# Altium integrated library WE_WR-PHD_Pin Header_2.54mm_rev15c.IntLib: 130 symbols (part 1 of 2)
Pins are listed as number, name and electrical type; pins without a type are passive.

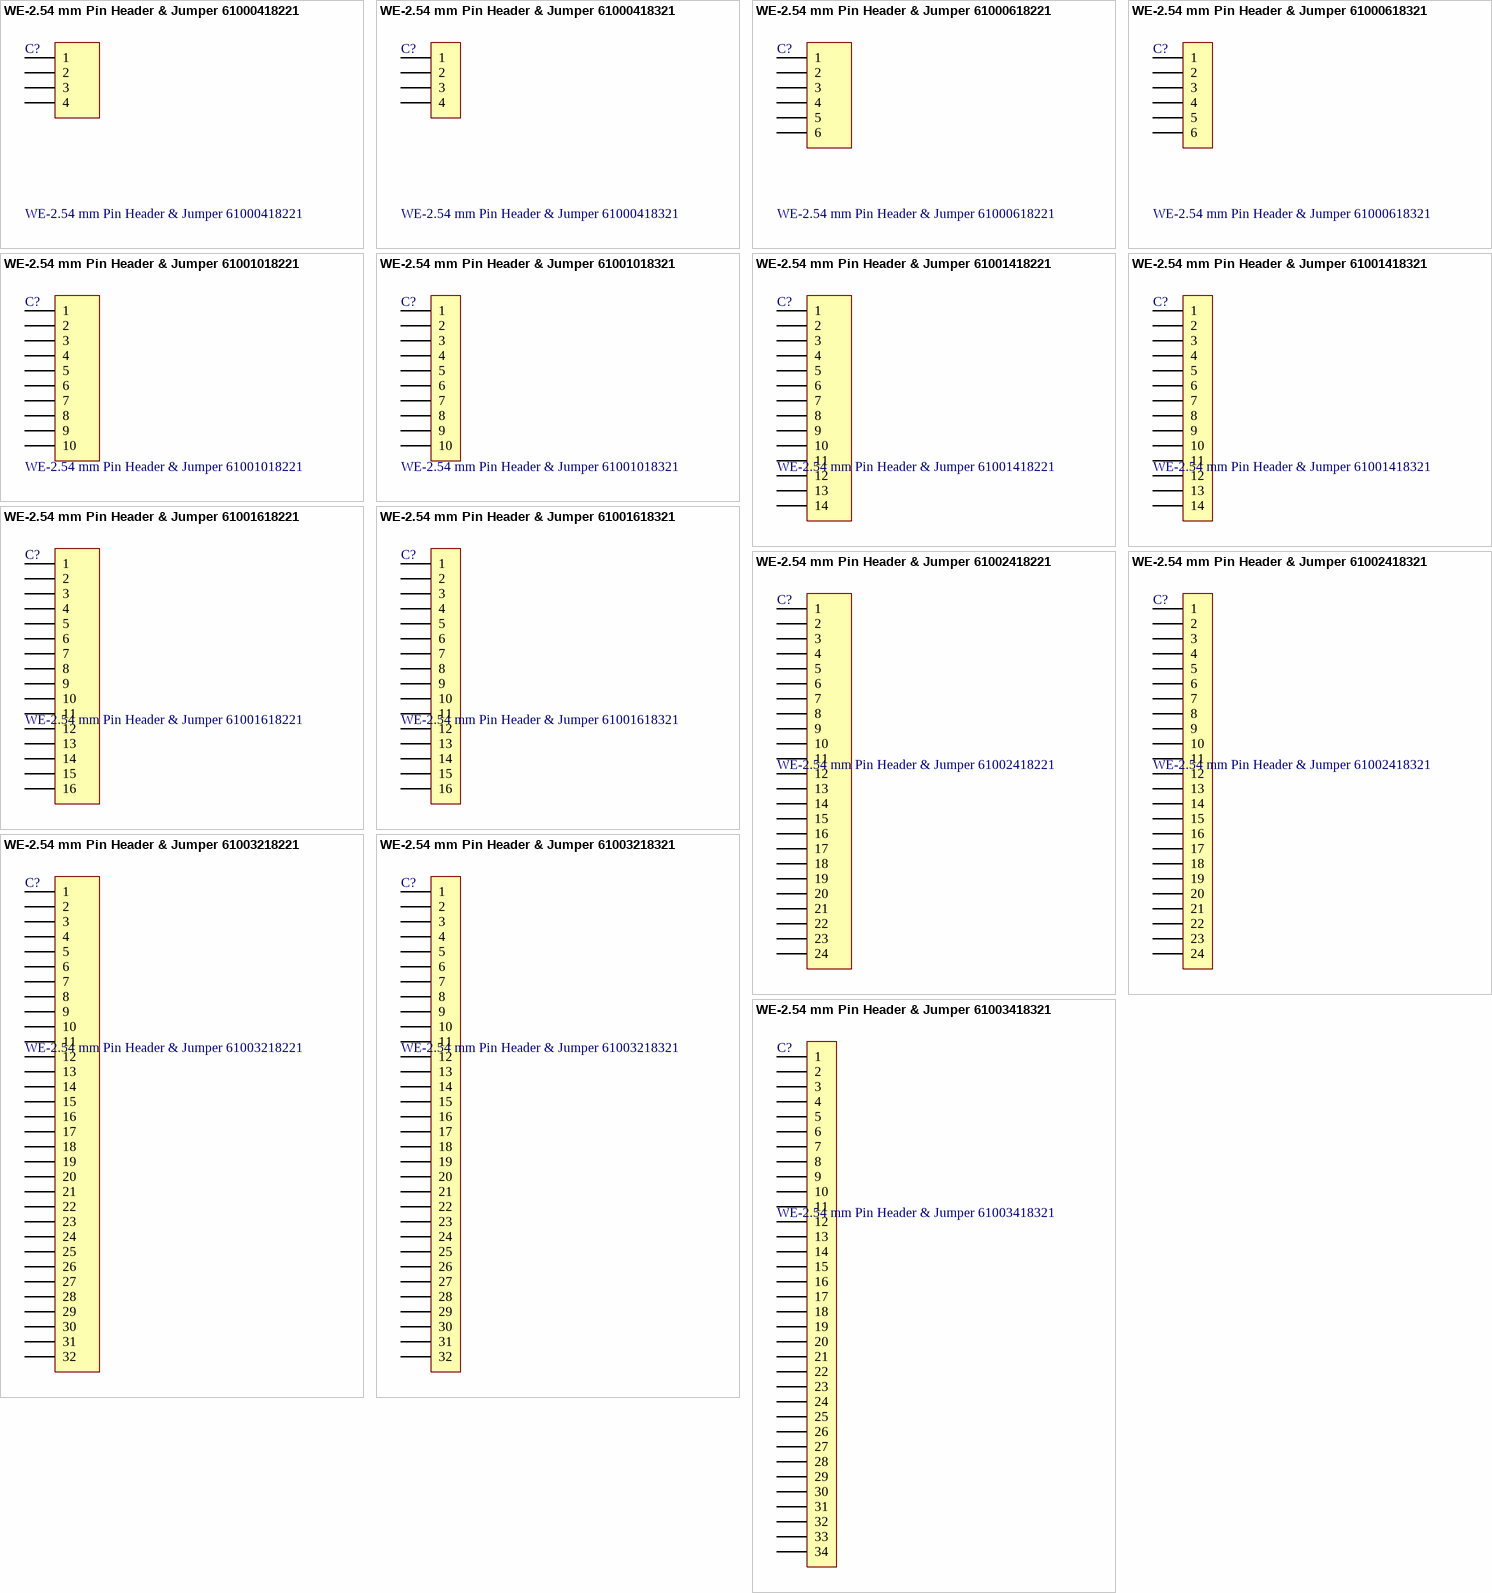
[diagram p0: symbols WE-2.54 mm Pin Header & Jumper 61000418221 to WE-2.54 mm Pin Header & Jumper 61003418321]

## WE-2.54 mm Pin Header & Jumper 61000418221
designator C?
WR-PHD 2.54 mm SMT Pin Header; Manufacturer: Würth Elektronik eiSos GmbH; ComponentLink1 Description: Manufacturer; ComponentLink2 Description: Datasheet; NoPins: 04
footprint 61000418221 (SMT, 4 pins, 1 row, straight, Type 1, gold plating)
pins: 1, 2, 3, 4

## WE-2.54 mm Pin Header & Jumper 61000418321
designator C?
WR-PHD 2.54 mm SMT Pin Header; Manufacturer: Würth Elektronik eiSos GmbH; ComponentLink1 Description: Manufacturer; ComponentLink2 Description: Datasheet; NoPins: 04
footprint 61000418321 (SMT, 4 pins, 1 row, straight, Type 2, gold plating)
pins: 1, 2, 3, 4

## WE-2.54 mm Pin Header & Jumper 61000618221
designator C?
WR-PHD 2.54 mm SMT Pin Header; Manufacturer: Würth Elektronik eiSos GmbH; ComponentLink1 Description: Manufacturer; ComponentLink2 Description: Datasheet; NoPins: 06
footprint 61000618221 (SMT, 6 pins, 1 row, straight, Type 1, gold plating)
pins: 1, 2, 3, 4, 5, 6

## WE-2.54 mm Pin Header & Jumper 61000618321
designator C?
WR-PHD 2.54 mm SMT Pin Header; Manufacturer: Würth Elektronik eiSos GmbH; ComponentLink1 Description: Manufacturer; ComponentLink2 Description: Datasheet; NoPins: 06
footprint 61000618321 (SMT, 6 pins, 1 row, straight, Type 2, gold plating)
pins: 1, 2, 3, 4, 5, 6

## WE-2.54 mm Pin Header & Jumper 61001018221
designator C?
WR-PHD 2.54 mm SMT Pin Header; Manufacturer: Würth Elektronik eiSos GmbH; ComponentLink1 Description: Manufacturer; ComponentLink2 Description: Datasheet; NoPins: 10
footprint 61001018221 (SMT, 10 pins, 1 row, straight, Type 1, gold plating)
pins: 1, 2, 3, 4, 5, 6, 7, 8, 9, 10

## WE-2.54 mm Pin Header & Jumper 61001018321
designator C?
WR-PHD 2.54 mm SMT Pin Header; Manufacturer: Würth Elektronik eiSos GmbH; ComponentLink1 Description: Manufacturer; ComponentLink2 Description: Datasheet; NoPins: 10
footprint 61001018321 (SMT, 10 pins, 1 row, straight, Type 2, gold plating)
pins: 1, 2, 3, 4, 5, 6, 7, 8, 9, 10

## WE-2.54 mm Pin Header & Jumper 61001418221
designator C?
WR-PHD 2.54 mm SMT Pin Header; Manufacturer: Würth Elektronik eiSos GmbH; ComponentLink1 Description: Manufacturer; ComponentLink2 Description: Datasheet; NoPins: 14
footprint 61001418221 (SMT, 14 pins, 1 row, straight, Type 1, gold plating)
pins: 1, 2, 3, 4, 5, 6, 7, 8, 9, 10, 11, 12, 13, 14

## WE-2.54 mm Pin Header & Jumper 61001418321
designator C?
WR-PHD 2.54 mm SMT Pin Header; Manufacturer: Würth Elektronik eiSos GmbH; ComponentLink1 Description: Manufacturer; ComponentLink2 Description: Datasheet; NoPins: 14
footprint 61001418321 (SMT, 14 pins, 1 row, straight, Type 2, gold plating)
pins: 1, 2, 3, 4, 5, 6, 7, 8, 9, 10, 11, 12, 13, 14

## WE-2.54 mm Pin Header & Jumper 61001618221
designator C?
WR-PHD 2.54 mm SMT Pin Header; Manufacturer: Würth Elektronik eiSos GmbH; ComponentLink1 Description: Manufacturer; ComponentLink2 Description: Datasheet; NoPins: 16
footprint 61001618221 (SMT, 16 pins, 1 row, straight, Type 1, gold plating)
pins: 1, 2, 3, 4, 5, 6, 7, 8, 9, 10, 11, 12, 13, 14, 15, 16

## WE-2.54 mm Pin Header & Jumper 61001618321
designator C?
WR-PHD 2.54 mm SMT Pin Header; Manufacturer: Würth Elektronik eiSos GmbH; ComponentLink1 Description: Manufacturer; ComponentLink2 Description: Datasheet; NoPins: 16
footprint 61001618321 (SMT, 16 pins, 1 row, straight, Type 2, gold plating)
pins: 1, 2, 3, 4, 5, 6, 7, 8, 9, 10, 11, 12, 13, 14, 15, 16

## WE-2.54 mm Pin Header & Jumper 61002418221
designator C?
WR-PHD 2.54 mm SMT Pin Header; Manufacturer: Würth Elektronik eiSos GmbH; ComponentLink1 Description: Manufacturer; ComponentLink2 Description: Datasheet; NoPins: 24
footprint 61002418221 (SMT, 24 pins, 1 row, straight, Type 1, gold plating)
pins: 1, 2, 3, 4, 5, 6, 7, 8, 9, 10, 11, 12, 13, 14, 15, 16, 17, 18, 19, 20, 21, 22, 23, 24

## WE-2.54 mm Pin Header & Jumper 61002418321
designator C?
WR-PHD 2.54 mm SMT Pin Header; Manufacturer: Würth Elektronik eiSos GmbH; ComponentLink1 Description: Manufacturer; ComponentLink2 Description: Datasheet; NoPins: 24
footprint 61002418321 (SMT, 24 pins, 1 row, straight, Type 2, gold plating)
pins: 1, 2, 3, 4, 5, 6, 7, 8, 9, 10, 11, 12, 13, 14, 15, 16, 17, 18, 19, 20, 21, 22, 23, 24

## WE-2.54 mm Pin Header & Jumper 61003218221
designator C?
WR-PHD 2.54 mm SMT Pin Header; Manufacturer: Würth Elektronik eiSos GmbH; ComponentLink1 Description: Manufacturer; ComponentLink2 Description: Datasheet; NoPins: 32
footprint 61003218221 (SMT, 32 pins, 1 row, straight, Type 1, gold plating)
pins: 1, 2, 3, 4, 5, 6, 7, 8, 9, 10, 11, 12, 13, 14, 15, 16, 17, 18, 19, 20, 21, 22, 23, 24, 25, 26, 27, 28, 29, 30, 31, 32

## WE-2.54 mm Pin Header & Jumper 61003218321
designator C?
WR-PHD 2.54 mm SMT Pin Header; Manufacturer: Würth Elektronik eiSos GmbH; ComponentLink1 Description: Manufacturer; ComponentLink2 Description: Datasheet; NoPins: 32
footprint 61003218321 (SMT, 32 pins, 1 row, straight, Type 2, gold plating)
pins: 1, 2, 3, 4, 5, 6, 7, 8, 9, 10, 11, 12, 13, 14, 15, 16, 17, 18, 19, 20, 21, 22, 23, 24, 25, 26, 27, 28, 29, 30, 31, 32

## WE-2.54 mm Pin Header & Jumper 61003418321
designator C?
WR-PHD 2.54 mm SMT Pin Header; Manufacturer: Würth Elektronik eiSos GmbH; ComponentLink1 Description: Manufacturer; ComponentLink2 Description: Datasheet; NoPins: 34
footprint 61003418321 (SMT, 34 pins, 1 row, straight, Type 2, gold plating)
pins: 1, 2, 3, 4, 5, 6, 7, 8, 9, 10, 11, 12, 13, 14, 15, 16, 17, 18, 19, 20, 21, 22, 23, 24, 25, 26, 27, 28, 29, 30, 31, 32, 33, 34

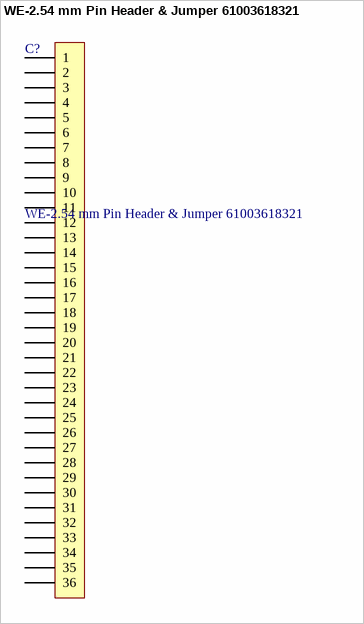
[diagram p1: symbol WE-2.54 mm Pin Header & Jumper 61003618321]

## WE-2.54 mm Pin Header & Jumper 61003618321
designator C?
WR-PHD 2.54 mm SMT Pin Header; Manufacturer: Würth Elektronik eiSos GmbH; ComponentLink1 Description: Manufacturer; ComponentLink2 Description: Datasheet; NoPins: 36
footprint 61003618321 (SMT, 36 pins, 1 row, straight, Type 2, gold plating)
pins: 1, 2, 3, 4, 5, 6, 7, 8, 9, 10, 11, 12, 13, 14, 15, 16, 17, 18, 19, 20, 21, 22, 23, 24, 25, 26, 27, 28, 29, 30, 31, 32, 33, 34, 35, 36


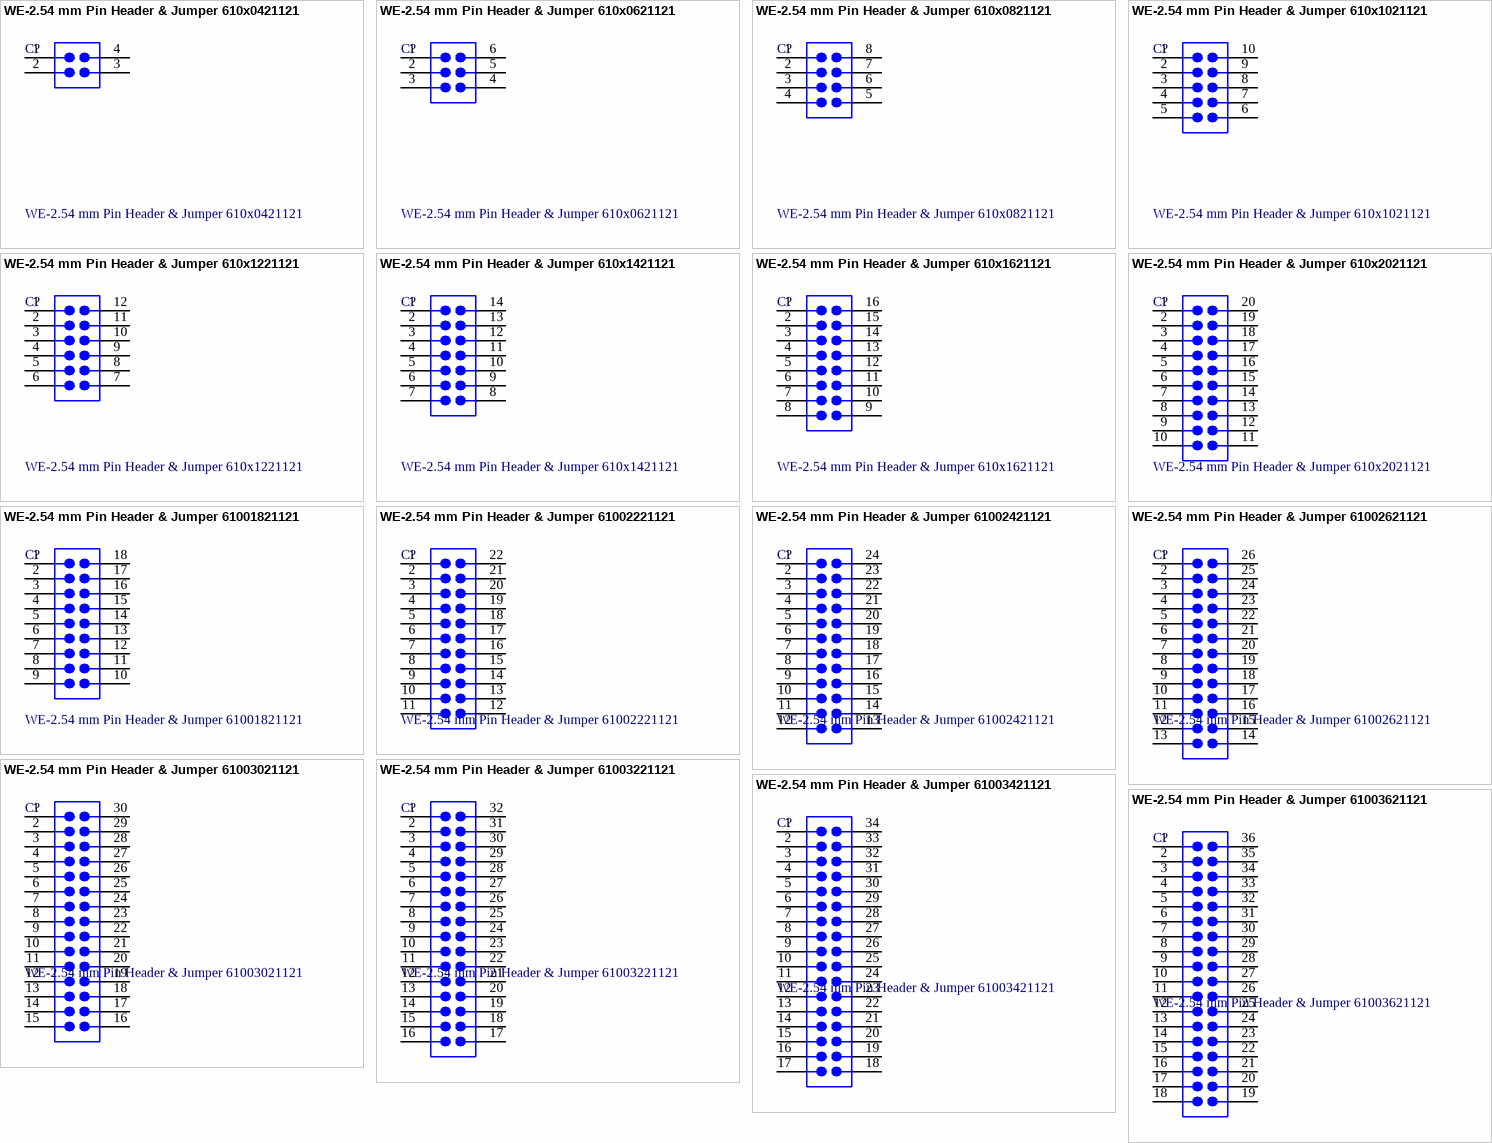
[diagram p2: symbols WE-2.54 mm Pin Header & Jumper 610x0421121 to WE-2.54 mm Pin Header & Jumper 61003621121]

## WE-2.54 mm Pin Header & Jumper 610x0421121
designator C?
WR-PHD 2.54 mm Dual SMT Pin Header; Manufacturer: Würth Elektronik eiSos GmbH; ComponentLink1 Description: Manufacturer; ComponentLink2 Description: Datasheet; NoPins: 04
footprint 610x0421121 (SMT, 4 pins, dual row, straight, gold plating)
pins: 1, 2, 3, 4

## WE-2.54 mm Pin Header & Jumper 610x0621121
designator C?
WR-PHD 2.54 mm Dual SMT Pin Header; Manufacturer: Würth Elektronik eiSos GmbH; ComponentLink1 Description: Manufacturer; ComponentLink2 Description: Datasheet; NoPins: 06
footprint 610x0621121 (SMT, 6 pins, dual row, straight, gold plating)
pins: 1, 2, 3, 4, 5, 6

## WE-2.54 mm Pin Header & Jumper 610x0821121
designator C?
WR-PHD 2.54 mm Dual SMT Pin Header; Manufacturer: Würth Elektronik eiSos GmbH; ComponentLink1 Description: Manufacturer; ComponentLink2 Description: Datasheet; NoPins: 08
footprint 610x0821121 (SMT, 8 pins, dual row, straight, gold plating)
pins: 1, 2, 3, 4, 5, 6, 7, 8

## WE-2.54 mm Pin Header & Jumper 610x1021121
designator C?
WR-PHD 2.54 mm Dual SMT Pin Header; Manufacturer: Würth Elektronik eiSos GmbH; ComponentLink1 Description: Manufacturer; ComponentLink2 Description: Datasheet; NoPins: 10
footprint 610x1021121 (SMT, 10 pins, dual row, straight, gold plating)
pins: 1, 2, 3, 4, 5, 6, 7, 8, 9, 10

## WE-2.54 mm Pin Header & Jumper 610x1221121
designator C?
WR-PHD 2.54 mm Dual SMT Pin Header; Manufacturer: Würth Elektronik eiSos GmbH; ComponentLink1 Description: Manufacturer; ComponentLink2 Description: Datasheet; NoPins: 12
footprint 610x1221121 (SMT, 12  pins, dual row, straight, gold plating)
pins: 1, 2, 3, 4, 5, 6, 7, 8, 9, 10, 11, 12

## WE-2.54 mm Pin Header & Jumper 610x1421121
designator C?
WR-PHD 2.54 mm Dual SMT Pin Header; Manufacturer: Würth Elektronik eiSos GmbH; ComponentLink1 Description: Manufacturer; ComponentLink2 Description: Datasheet; NoPins: 14
footprint 610x1421121 (SMT, 14 pins, dual row, straight, gold plating)
pins: 1, 2, 3, 4, 5, 6, 7, 8, 9, 10, 11, 12, 13, 14

## WE-2.54 mm Pin Header & Jumper 610x1621121
designator C?
WR-PHD 2.54 mm Dual SMT Pin Header; Manufacturer: Würth Elektronik eiSos GmbH; ComponentLink1 Description: Manufacturer; ComponentLink2 Description: Datasheet; NoPins: 16
footprint 610x1621121 (SMT, 16 pins, dual row, straight, gold plating)
pins: 1, 2, 3, 4, 5, 6, 7, 8, 9, 10, 11, 12, 13, 14, 15, 16

## WE-2.54 mm Pin Header & Jumper 610x2021121
designator C?
WR-PHD 2.54 mm Dual SMT Pin Header; Manufacturer: Würth Elektronik eiSos GmbH; ComponentLink1 Description: Manufacturer; ComponentLink2 Description: Datasheet; NoPins: 20
footprint 610x2021121 (SMT, 20 pins, dual row, straight, gold plating)
pins: 1, 2, 3, 4, 5, 6, 7, 8, 9, 10, 11, 12, 13, 14, 15, 16, 17, 18, 19, 20

## WE-2.54 mm Pin Header & Jumper 61001821121
designator C?
WR-PHD 2.54 mm Dual SMT Pin Header; Manufacturer: Würth Elektronik eiSos GmbH; ComponentLink1 Description: Manufacturer; ComponentLink2 Description: Datasheet; NoPins: 18
footprint 61001821121 (SMT, 18 pins, dual row, straight, gold plating)
pins: 1, 2, 3, 4, 5, 6, 7, 8, 9, 10, 11, 12, 13, 14, 15, 16, 17, 18

## WE-2.54 mm Pin Header & Jumper 61002221121
designator C?
WR-PHD 2.54 mm Dual SMT Pin Header; Manufacturer: Würth Elektronik eiSos GmbH; ComponentLink1 Description: Manufacturer; ComponentLink2 Description: Datasheet; NoPins: 22
footprint 61002221121 (SMT, 22 pins, dual row, straight, gold plating)
pins: 1, 2, 3, 4, 5, 6, 7, 8, 9, 10, 11, 12, 13, 14, 15, 16, 17, 18, 19, 20, 21, 22

## WE-2.54 mm Pin Header & Jumper 61002421121
designator C?
WR-PHD 2.54 mm Dual SMT Pin Header; Manufacturer: Würth Elektronik eiSos GmbH; ComponentLink1 Description: Manufacturer; ComponentLink2 Description: Datasheet; NoPins: 24
footprint 61002421121 (SMT, 24 pins, dual row, straight, gold plating)
pins: 1, 2, 3, 4, 5, 6, 7, 8, 9, 10, 11, 12, 13, 14, 15, 16, 17, 18, 19, 20, 21, 22, 23, 24

## WE-2.54 mm Pin Header & Jumper 61002621121
designator C?
WR-PHD 2.54 mm Dual SMT Pin Header; Manufacturer: Würth Elektronik eiSos GmbH; ComponentLink1 Description: Manufacturer; ComponentLink2 Description: Datasheet; NoPins: 26
footprint 61002621121 (SMT, 26 pins, dual row, straight, gold plating)
pins: 1, 2, 3, 4, 5, 6, 7, 8, 9, 10, 11, 12, 13, 14, 15, 16, 17, 18, 19, 20, 21, 22, 23, 24, 25, 26

## WE-2.54 mm Pin Header & Jumper 61003021121
designator C?
WR-PHD 2.54 mm Dual SMT Pin Header; Manufacturer: Würth Elektronik eiSos GmbH; ComponentLink1 Description: Manufacturer; ComponentLink2 Description: Datasheet; NoPins: 30
footprint 61003021121 (SMT, 30 pins, dual row, straight, gold plating)
pins: 1, 2, 3, 4, 5, 6, 7, 8, 9, 10, 11, 12, 13, 14, 15, 16, 17, 18, 19, 20, 21, 22, 23, 24, 25, 26, 27, 28, 29, 30

## WE-2.54 mm Pin Header & Jumper 61003221121
designator C?
WR-PHD 2.54 mm Dual SMT Pin Header; Manufacturer: Würth Elektronik eiSos GmbH; ComponentLink1 Description: Manufacturer; ComponentLink2 Description: Datasheet; NoPins: 32
footprint 61003221121 (SMT, 32 pins, dual row, straight, gold plating)
pins: 1, 2, 3, 4, 5, 6, 7, 8, 9, 10, 11, 12, 13, 14, 15, 16, 17, 18, 19, 20, 21, 22, 23, 24, 25, 26, 27, 28, 29, 30, 31, 32

## WE-2.54 mm Pin Header & Jumper 61003421121
designator C?
WR-PHD 2.54 mm Dual SMT Pin Header; Manufacturer: Würth Elektronik eiSos GmbH; ComponentLink1 Description: Manufacturer; ComponentLink2 Description: Datasheet; NoPins: 34
footprint 61003421121 (SMT, 34 pins, dual row, straight, gold plating)
pins: 1, 2, 3, 4, 5, 6, 7, 8, 9, 10, 11, 12, 13, 14, 15, 16, 17, 18, 19, 20, 21, 22, 23, 24, 25, 26, 27, 28, 29, 30, 31, 32, 33, 34

## WE-2.54 mm Pin Header & Jumper 61003621121
designator C?
WR-PHD 2.54 mm Dual SMT Pin Header; Manufacturer: Würth Elektronik eiSos GmbH; ComponentLink1 Description: Manufacturer; ComponentLink2 Description: Datasheet; NoPins: 36
footprint 61003621121 (SMT, 36 pins, dual row, straight, gold plating)
pins: 1, 2, 3, 4, 5, 6, 7, 8, 9, 10, 11, 12, 13, 14, 15, 16, 17, 18, 19, 20, 21, 22, 23, 24, 25, 26, 27, 28, 29, 30, 31, 32, 33, 34, 35, 36


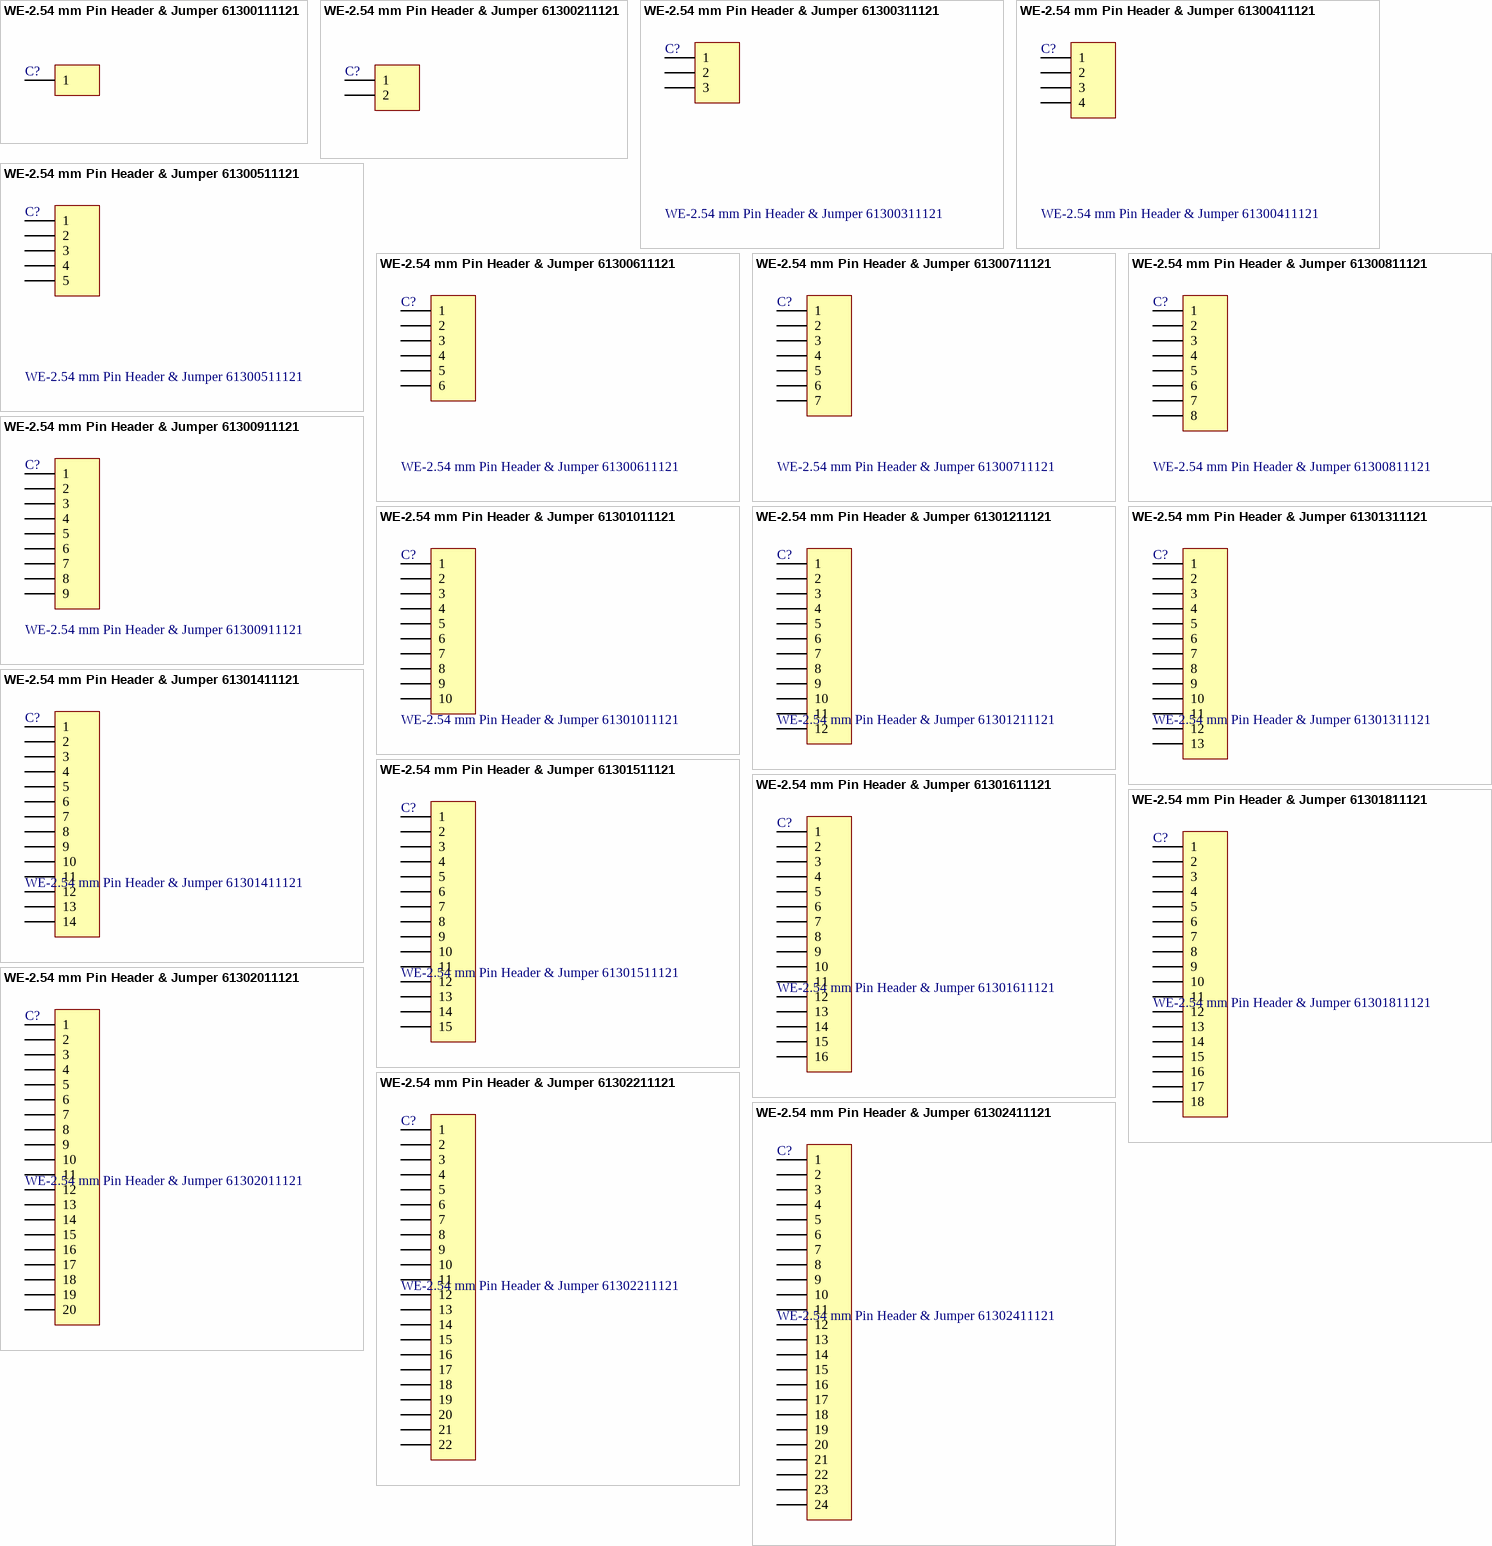
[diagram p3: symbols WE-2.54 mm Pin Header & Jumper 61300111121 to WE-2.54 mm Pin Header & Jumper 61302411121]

## WE-2.54 mm Pin Header & Jumper 61300111121
designator C?
WR-PHD 2.54mm Pin Header; Manufacturer: Würth Elektronik eiSos GmbH; ComponentLink1 Description: Manufacturer; ComponentLink2 Description: Datasheet; NoPins: 01
footprint 61300111121 (1pins, 1 row, straight, gold plating)
pins: 1

## WE-2.54 mm Pin Header & Jumper 61300211121
designator C?
WR-PHD 2.54mm Pin Header; Manufacturer: Würth Elektronik eiSos GmbH; ComponentLink1 Description: Manufacturer; ComponentLink2 Description: Datasheet; NoPins: 02
footprint 61300211121 (2 pins, 1 row, straight, gold plating)
pins: 1, 2

## WE-2.54 mm Pin Header & Jumper 61300311121
designator C?
WR-PHD 2.54mm Pin Header; Manufacturer: Würth Elektronik eiSos GmbH; ComponentLink1 Description: Manufacturer; ComponentLink2 Description: Datasheet; NoPins: 03
footprint 61300311121 (3 pins, 1 row, straight, gold plating)
pins: 1, 2, 3

## WE-2.54 mm Pin Header & Jumper 61300411121
designator C?
WR-PHD 2.54mm Pin Header; Manufacturer: Würth Elektronik eiSos GmbH; ComponentLink1 Description: Manufacturer; ComponentLink2 Description: Datasheet; NoPins: 04
footprint 61300411121 (4 pins, 1 row, straight, gold plating)
pins: 1, 2, 3, 4

## WE-2.54 mm Pin Header & Jumper 61300511121
designator C?
WR-PHD 2.54mm Pin Header; Manufacturer: Würth Elektronik eiSos GmbH; ComponentLink1 Description: Manufacturer; ComponentLink2 Description: Datasheet; NoPins: 05
footprint 61300511121 (5 pins, 1 row, straight, gold plating)
pins: 1, 2, 3, 4, 5

## WE-2.54 mm Pin Header & Jumper 61300611121
designator C?
WR-PHD 2.54mm Pin Header; Manufacturer: Würth Elektronik eiSos GmbH; ComponentLink1 Description: Manufacturer; ComponentLink2 Description: Datasheet; NoPins: 06
footprint 61300611121 (6 pins, 1 row, straight, gold plating)
pins: 1, 2, 3, 4, 5, 6

## WE-2.54 mm Pin Header & Jumper 61300711121
designator C?
WR-PHD 2.54mm Pin Header; Manufacturer: Würth Elektronik eiSos GmbH; ComponentLink1 Description: Manufacturer; ComponentLink2 Description: Datasheet; NoPins: 07
footprint 61300711121 (7 pins, 1 row, straight, gold plating)
pins: 1, 2, 3, 4, 5, 6, 7

## WE-2.54 mm Pin Header & Jumper 61300811121
designator C?
WR-PHD 2.54mm Pin Header; Manufacturer: Würth Elektronik eiSos GmbH; ComponentLink1 Description: Manufacturer; ComponentLink2 Description: Datasheet; NoPins: 08
footprint 61300811121 (8 pins, 1 row, straight, gold plating)
pins: 1, 2, 3, 4, 5, 6, 7, 8

## WE-2.54 mm Pin Header & Jumper 61300911121
designator C?
WR-PHD 2.54mm Pin Header; Manufacturer: Würth Elektronik eiSos GmbH; ComponentLink1 Description: Manufacturer; ComponentLink2 Description: Datasheet; NoPins: 09
footprint 61300911121 (9 pins, 1 row, straight, gold plating)
pins: 1, 2, 3, 4, 5, 6, 7, 8, 9

## WE-2.54 mm Pin Header & Jumper 61301011121
designator C?
WR-PHD 2.54mm Pin Header; Manufacturer: Würth Elektronik eiSos GmbH; ComponentLink1 Description: Manufacturer; ComponentLink2 Description: Datasheet; NoPins: 10
footprint 61301011121 (10 pins, 1 row, straight, gold plating)
pins: 1, 2, 3, 4, 5, 6, 7, 8, 9, 10

## WE-2.54 mm Pin Header & Jumper 61301211121
designator C?
WR-PHD 2.54mm Pin Header; Manufacturer: Würth Elektronik eiSos GmbH; ComponentLink1 Description: Manufacturer; ComponentLink2 Description: Datasheet; NoPins: 12
footprint 61301211121 (12 pins, 1 row, straight, gold plating)
pins: 1, 2, 3, 4, 5, 6, 7, 8, 9, 10, 11, 12

## WE-2.54 mm Pin Header & Jumper 61301311121
designator C?
WR-PHD 2.54mm Pin Header; Manufacturer: Würth Elektronik eiSos GmbH; ComponentLink1 Description: Manufacturer; ComponentLink2 Description: Datasheet; NoPins: 13
footprint 61301311121 (13 pins, 1 row, straight, gold plating)
pins: 1, 2, 3, 4, 5, 6, 7, 8, 9, 10, 11, 12, 13

## WE-2.54 mm Pin Header & Jumper 61301411121
designator C?
WR-PHD 2.54mm Pin Header; Manufacturer: Würth Elektronik eiSos GmbH; ComponentLink1 Description: Manufacturer; ComponentLink2 Description: Datasheet; NoPins: 14
footprint 61301411121 (14 pins, 1 row, straight, gold plating)
pins: 1, 2, 3, 4, 5, 6, 7, 8, 9, 10, 11, 12, 13, 14

## WE-2.54 mm Pin Header & Jumper 61301511121
designator C?
WR-PHD 2.54mm Pin Header; Manufacturer: Würth Elektronik eiSos GmbH; ComponentLink1 Description: Manufacturer; ComponentLink2 Description: Datasheet; NoPins: 01
footprint 61301511121 (15  pins, 1 row, straight, gold plating)
pins: 1, 2, 3, 4, 5, 6, 7, 8, 9, 10, 11, 12, 13, 14, 15

## WE-2.54 mm Pin Header & Jumper 61301611121
designator C?
WR-PHD 2.54mm Pin Header; Manufacturer: Würth Elektronik eiSos GmbH; ComponentLink1 Description: Manufacturer; ComponentLink2 Description: Datasheet; NoPins: 16
footprint 61301611121 (16  pins, 1 row, straight, gold plating)
pins: 1, 2, 3, 4, 5, 6, 7, 8, 9, 10, 11, 12, 13, 14, 15, 16

## WE-2.54 mm Pin Header & Jumper 61301811121
designator C?
WR-PHD 2.54mm Pin Header; Manufacturer: Würth Elektronik eiSos GmbH; ComponentLink1 Description: Manufacturer; ComponentLink2 Description: Datasheet; NoPins: 18
footprint 61301811121 (18 pins, 1 row, straight, gold plating)
pins: 1, 2, 3, 4, 5, 6, 7, 8, 9, 10, 11, 12, 13, 14, 15, 16, 17, 18

## WE-2.54 mm Pin Header & Jumper 61302011121
designator C?
WR-PHD 2.54mm Pin Header; Manufacturer: Würth Elektronik eiSos GmbH; ComponentLink1 Description: Manufacturer; ComponentLink2 Description: Datasheet; NoPins: 20
footprint 61302011121 (20 pins, 1 row, straight, gold plating)
pins: 1, 2, 3, 4, 5, 6, 7, 8, 9, 10, 11, 12, 13, 14, 15, 16, 17, 18, 19, 20

## WE-2.54 mm Pin Header & Jumper 61302211121
designator C?
WR-PHD 2.54mm Pin Header; Manufacturer: Würth Elektronik eiSos GmbH; ComponentLink1 Description: Manufacturer; ComponentLink2 Description: Datasheet; NoPins: 22
footprint 61302211121 (22 pins, 1 row, straight, gold plating)
pins: 1, 2, 3, 4, 5, 6, 7, 8, 9, 10, 11, 12, 13, 14, 15, 16, 17, 18, 19, 20, 21, 22

## WE-2.54 mm Pin Header & Jumper 61302411121
designator C?
WR-PHD 2.54mm Pin Header; Manufacturer: Würth Elektronik eiSos GmbH; ComponentLink1 Description: Manufacturer; ComponentLink2 Description: Datasheet; NoPins: 24
footprint 61302411121 (24 pins, 1 row, straight, gold plating)
pins: 1, 2, 3, 4, 5, 6, 7, 8, 9, 10, 11, 12, 13, 14, 15, 16, 17, 18, 19, 20, 21, 22, 23, 24

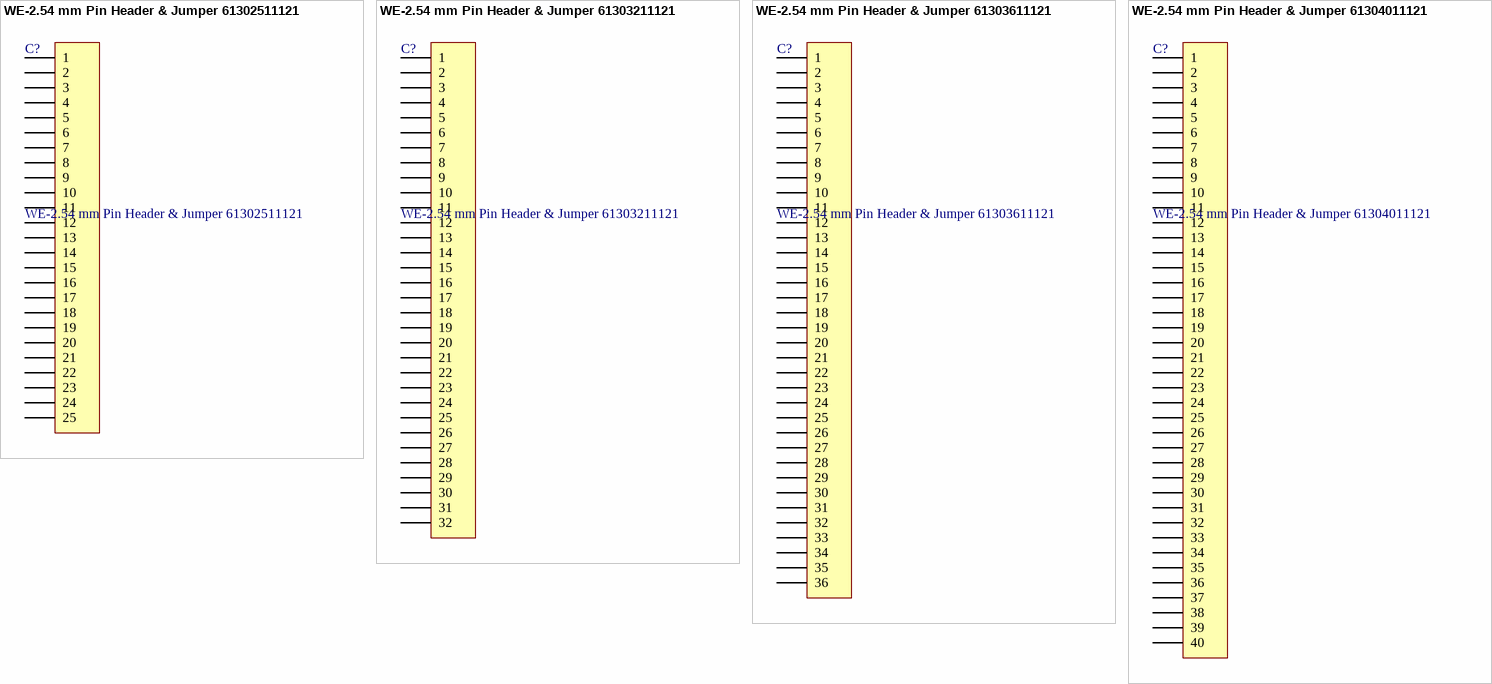
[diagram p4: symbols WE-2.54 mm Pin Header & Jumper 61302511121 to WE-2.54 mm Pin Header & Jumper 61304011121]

## WE-2.54 mm Pin Header & Jumper 61302511121
designator C?
WR-PHD 2.54mm Pin Header; Manufacturer: Würth Elektronik eiSos GmbH; ComponentLink1 Description: Manufacturer; ComponentLink2 Description: Datasheet; NoPins: 25
footprint 61302511121 (25 pins, 1 row, straight, gold plating)
pins: 1, 2, 3, 4, 5, 6, 7, 8, 9, 10, 11, 12, 13, 14, 15, 16, 17, 18, 19, 20, 21, 22, 23, 24, 25

## WE-2.54 mm Pin Header & Jumper 61303211121
designator C?
WR-PHD 2.54mm Pin Header; Manufacturer: Würth Elektronik eiSos GmbH; ComponentLink1 Description: Manufacturer; ComponentLink2 Description: Datasheet; NoPins: 32
footprint 61303211121 (32 pins, 1 row, straight, gold plating)
pins: 1, 2, 3, 4, 5, 6, 7, 8, 9, 10, 11, 12, 13, 14, 15, 16, 17, 18, 19, 20, 21, 22, 23, 24, 25, 26, 27, 28, 29, 30, 31, 32

## WE-2.54 mm Pin Header & Jumper 61303611121
designator C?
WR-PHD 2.54mm Pin Header; Manufacturer: Würth Elektronik eiSos GmbH; ComponentLink1 Description: Manufacturer; ComponentLink2 Description: Datasheet; NoPins: 36
footprint 61303611121 (36 pins, 1 row, straight, gold plating)
pins: 1, 2, 3, 4, 5, 6, 7, 8, 9, 10, 11, 12, 13, 14, 15, 16, 17, 18, 19, 20, 21, 22, 23, 24, 25, 26, 27, 28, 29, 30, 31, 32, 33, 34, 35, 36

## WE-2.54 mm Pin Header & Jumper 61304011121
designator C?
WR-PHD 2.54mm Pin Header; Manufacturer: Würth Elektronik eiSos GmbH; ComponentLink1 Description: Manufacturer; ComponentLink2 Description: Datasheet; NoPins: 40
footprint 61304011121 (40 pins, 1 row, straight, gold plating)
pins: 1, 2, 3, 4, 5, 6, 7, 8, 9, 10, 11, 12, 13, 14, 15, 16, 17, 18, 19, 20, 21, 22, 23, 24, 25, 26, 27, 28, 29, 30, 31, 32, 33, 34, 35, 36, 37, 38, 39, 40


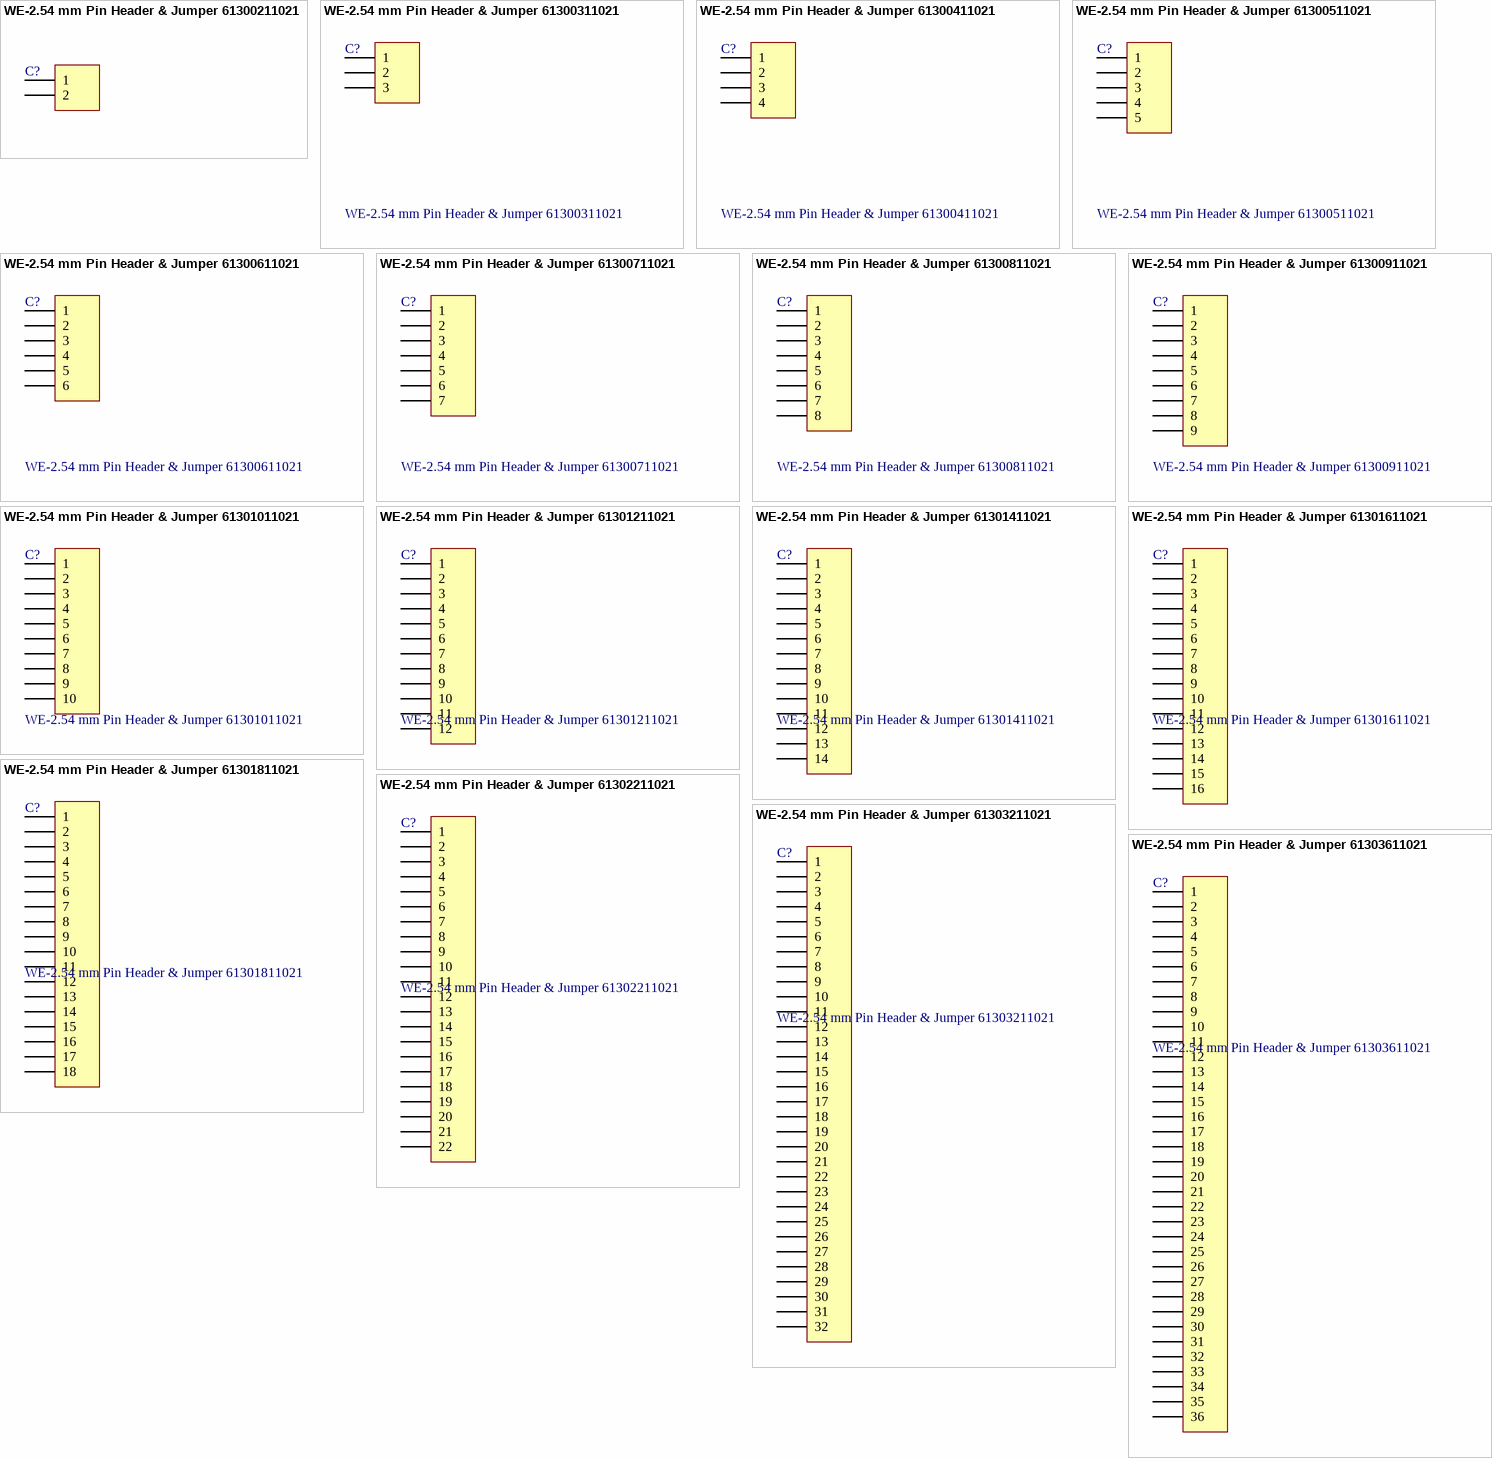
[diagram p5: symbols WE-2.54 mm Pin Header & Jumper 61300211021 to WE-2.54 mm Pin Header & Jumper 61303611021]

## WE-2.54 mm Pin Header & Jumper 61300211021
designator C?
WR-PHD 2.54mm Angled Pin Header; Manufacturer: Würth Elektronik eiSos GmbH; ComponentLink1 Description: Manufacturer; ComponentLink2 Description: Datasheet; NoPins: 02
footprint 61300211021 (2 pins, 1 row, right angled, gold plating)
pins: 1, 2

## WE-2.54 mm Pin Header & Jumper 61300311021
designator C?
WR-PHD 2.54mm Angled Pin Header; Manufacturer: Würth Elektronik eiSos GmbH; ComponentLink1 Description: Manufacturer; ComponentLink2 Description: Datasheet; NoPins: 03
footprint 61300311021 (3 pins, 1 row, right angled, gold plating)
pins: 1, 2, 3

## WE-2.54 mm Pin Header & Jumper 61300411021
designator C?
WR-PHD 2.54mm Angled Pin Header; Manufacturer: Würth Elektronik eiSos GmbH; ComponentLink1 Description: Manufacturer; ComponentLink2 Description: Datasheet; NoPins: 04
footprint 61300411021 (4 pins, 1 row, right angled, gold plating)
pins: 1, 2, 3, 4

## WE-2.54 mm Pin Header & Jumper 61300511021
designator C?
WR-PHD 2.54mm Angled Pin Header; Manufacturer: Würth Elektronik eiSos GmbH; ComponentLink1 Description: Manufacturer; ComponentLink2 Description: Datasheet; NoPins: 05
footprint 61300511021 (5 pins, 1 row, right angled, gold plating)
pins: 1, 2, 3, 4, 5

## WE-2.54 mm Pin Header & Jumper 61300611021
designator C?
WR-PHD 2.54mm Angled Pin Header; Manufacturer: Würth Elektronik eiSos GmbH; ComponentLink1 Description: Manufacturer; ComponentLink2 Description: Datasheet; NoPins: 06
footprint 61300611021 (6 pins, 1 row, right angled, gold plating)
pins: 1, 2, 3, 4, 5, 6

## WE-2.54 mm Pin Header & Jumper 61300711021
designator C?
WR-PHD 2.54mm Angled Pin Header; Manufacturer: Würth Elektronik eiSos GmbH; ComponentLink1 Description: Manufacturer; ComponentLink2 Description: Datasheet; NoPins: 07
footprint 61300711021 (7 pins, 1 row, right angled, gold plating)
pins: 1, 2, 3, 4, 5, 6, 7

## WE-2.54 mm Pin Header & Jumper 61300811021
designator C?
WR-PHD 2.54mm Angled Pin Header; Manufacturer: Würth Elektronik eiSos Gmb; ComponentLink1 Description: Manufacturer; ComponentLink2 Description: Datasheet; NoPins: 08
footprint 61300811021 (8 pins, 1 row, right angled, gold plating)
pins: 1, 2, 3, 4, 5, 6, 7, 8

## WE-2.54 mm Pin Header & Jumper 61300911021
designator C?
WR-PHD 2.54mm Angled Pin Header; Manufacturer: Würth Elektronik eiSos GmbH; ComponentLink1 Description: Manufacturer; ComponentLink2 Description: Datasheet; NoPins: 09
footprint 61300911021 (9 pins, 1 row, right angled, gold plating)
pins: 1, 2, 3, 4, 5, 6, 7, 8, 9

## WE-2.54 mm Pin Header & Jumper 61301011021
designator C?
WR-PHD 2.54mm Angled Pin Header; Manufacturer: Würth Elektronik eiSos GmbH; ComponentLink1 Description: Manufacturer; ComponentLink2 Description: Datasheet; NoPins: 10
footprint 61301011021 (10 pins, 1 row, right angled, gold plating)
pins: 1, 2, 3, 4, 5, 6, 7, 8, 9, 10

## WE-2.54 mm Pin Header & Jumper 61301211021
designator C?
WR-PHD 2.54mm Angled Pin Header; Manufacturer: Würth Elektronik eiSos GmbH; ComponentLink1 Description: Manufacturer; ComponentLink2 Description: Datasheet; NoPins: 12
footprint 61301211021 (12 pins, 1 row, right angled, gold plating)
pins: 1, 2, 3, 4, 5, 6, 7, 8, 9, 10, 11, 12

## WE-2.54 mm Pin Header & Jumper 61301411021
designator C?
WR-PHD 2.54mm Angled Pin Header; Manufacturer: Würth Elektronik eiSos GmbH; ComponentLink1 Description: Manufacturer; ComponentLink2 Description: Datasheet; NoPins: 14
footprint 61301411021 (14 pins, 1 row, right angled, gold plating)
pins: 1, 2, 3, 4, 5, 6, 7, 8, 9, 10, 11, 12, 13, 14

## WE-2.54 mm Pin Header & Jumper 61301611021
designator C?
WR-PHD 2.54mm Angled Pin Header; Manufacturer: Würth Elektronik eiSos GmbH; ComponentLink1 Description: Manufacturer; ComponentLink2 Description: Datasheet; NoPins: 16
footprint 61301611021 (16 pins, 1 row, right angled, gold plating)
pins: 1, 2, 3, 4, 5, 6, 7, 8, 9, 10, 11, 12, 13, 14, 15, 16

## WE-2.54 mm Pin Header & Jumper 61301811021
designator C?
WR-PHD 2.54mm Angled Pin Header; Manufacturer: Würth Elektronik eiSos GmbH; ComponentLink1 Description: Manufacturer; ComponentLink2 Description: Datasheet; NoPins: 18
footprint 61301811021 (18 pins, 1 row, right angled, gold plating)
pins: 1, 2, 3, 4, 5, 6, 7, 8, 9, 10, 11, 12, 13, 14, 15, 16, 17, 18

## WE-2.54 mm Pin Header & Jumper 61302211021
designator C?
WR-PHD 2.54mm Angled Pin Header; Manufacturer: Würth Elektronik eiSos GmbH; ComponentLink1 Description: Manufacturer; ComponentLink2 Description: Datasheet; NoPins: 22
footprint 61302211021 (22 pins, 1 row, right angled, gold plating)
pins: 1, 2, 3, 4, 5, 6, 7, 8, 9, 10, 11, 12, 13, 14, 15, 16, 17, 18, 19, 20, 21, 22

## WE-2.54 mm Pin Header & Jumper 61303211021
designator C?
WR-PHD 2.54mm Angled Pin Header; Manufacturer: Würth Elektronik eiSos GmbH; ComponentLink1 Description: Manufacturer; ComponentLink2 Description: Datasheet; NoPins: 32
footprint 61303211021 (32 pins, 1 row, right angled, gold plating)
pins: 1, 2, 3, 4, 5, 6, 7, 8, 9, 10, 11, 12, 13, 14, 15, 16, 17, 18, 19, 20, 21, 22, 23, 24, 25, 26, 27, 28, 29, 30, 31, 32

## WE-2.54 mm Pin Header & Jumper 61303611021
designator C?
WR-PHD 2.54mm Angled Pin Header; Manufacturer: Würth Elektronik eiSos GmbH; ComponentLink1 Description: Manufacturer; ComponentLink2 Description: Datasheet; NoPins: 36
footprint 61303611021 (36 pins, 1 row, right angled, gold plating)
pins: 1, 2, 3, 4, 5, 6, 7, 8, 9, 10, 11, 12, 13, 14, 15, 16, 17, 18, 19, 20, 21, 22, 23, 24, 25, 26, 27, 28, 29, 30, 31, 32, 33, 34, 35, 36

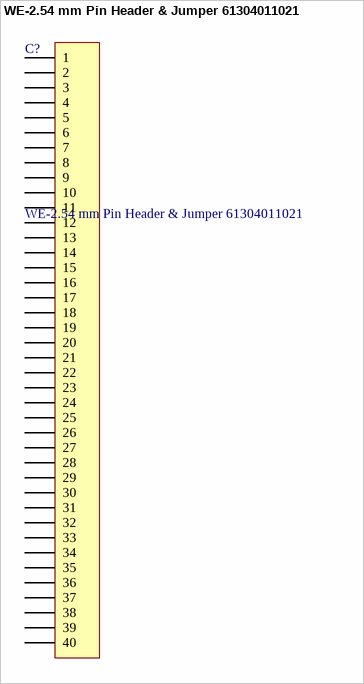
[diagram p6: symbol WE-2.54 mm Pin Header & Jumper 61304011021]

## WE-2.54 mm Pin Header & Jumper 61304011021
designator C?
WR-PHD 2.54mm Angled Pin Header; Manufacturer: Würth Elektronik eiSos GmbH; ComponentLink1 Description: Manufacturer; ComponentLink2 Description: Datasheet; NoPins: 40
footprint 61304011021 (40 pins, 1 row, right angled, gold plating)
pins: 1, 2, 3, 4, 5, 6, 7, 8, 9, 10, 11, 12, 13, 14, 15, 16, 17, 18, 19, 20, 21, 22, 23, 24, 25, 26, 27, 28, 29, 30, 31, 32, 33, 34, 35, 36, 37, 38, 39, 40


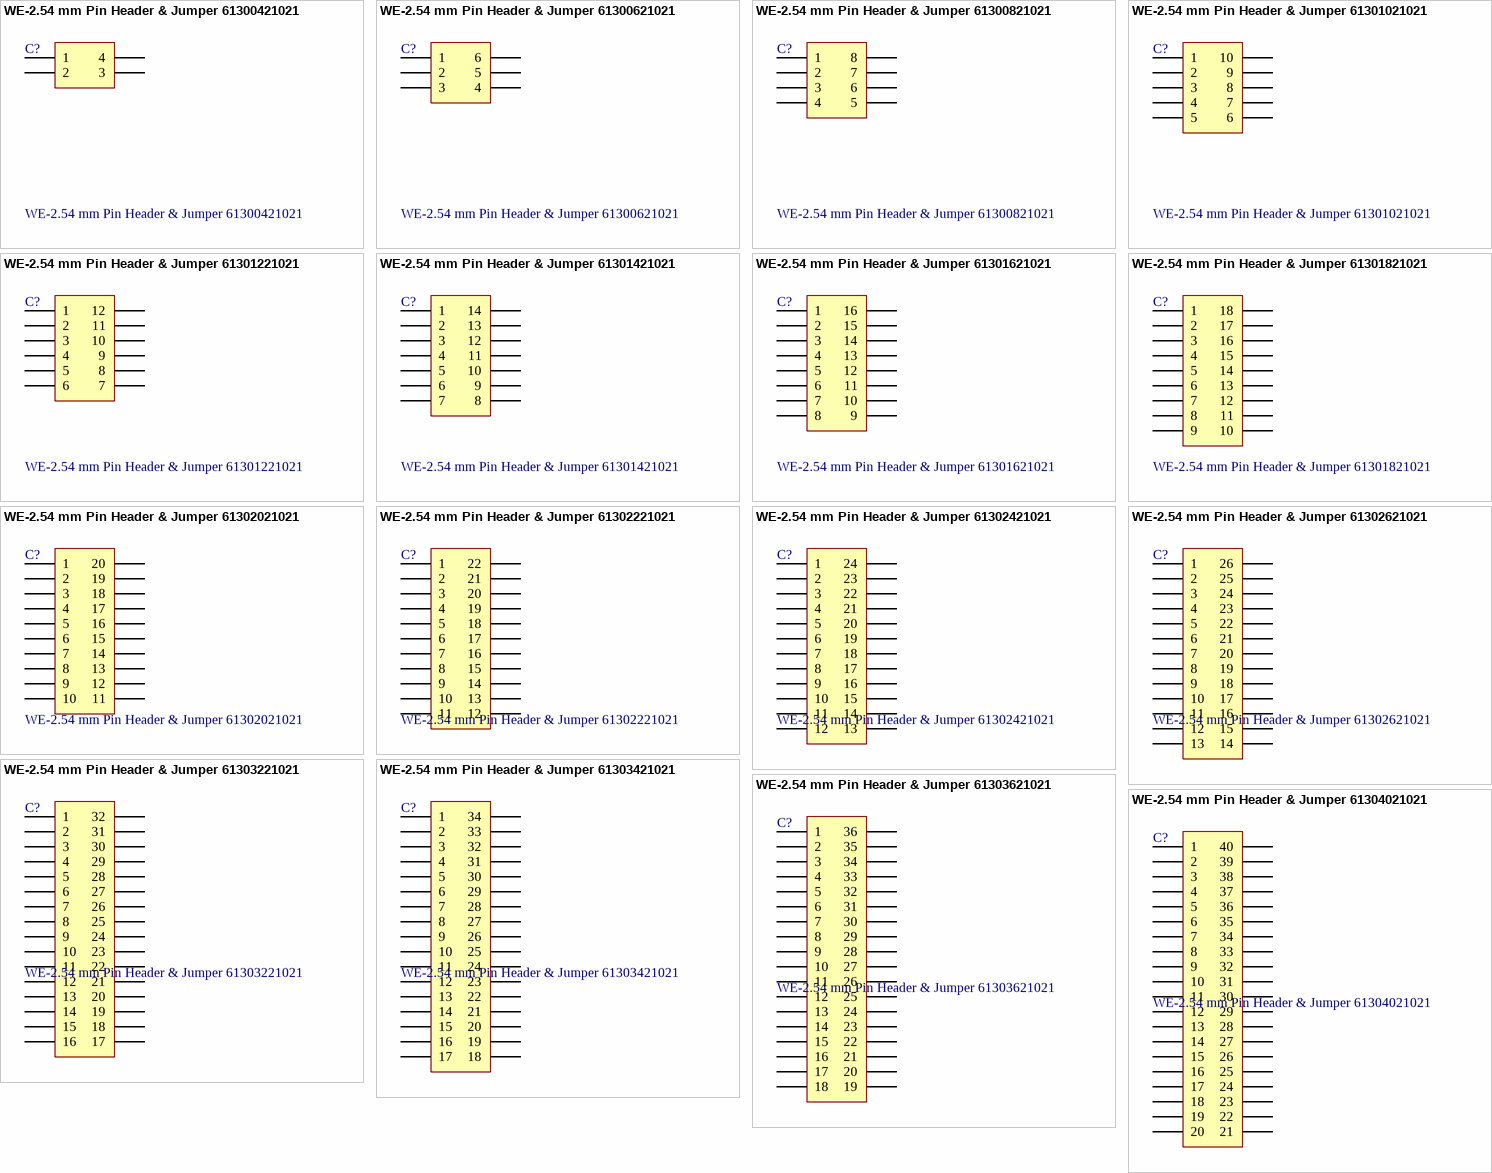
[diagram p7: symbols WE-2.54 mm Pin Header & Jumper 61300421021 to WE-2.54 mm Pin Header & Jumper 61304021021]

## WE-2.54 mm Pin Header & Jumper 61300421021
designator C?
WR-PHD 2.54 mm Angled Dual Pin Header; Manufacturer: Würth Elektronik eiSos GmbH; ComponentLink1 Description: Manufacturer; ComponentLink2 Description: Datasheet; NoPins: 04
footprint 61300421021 (4 pins, dual row, right angled, gold plating)
pins: 1, 2, 3, 4

## WE-2.54 mm Pin Header & Jumper 61300621021
designator C?
WR-PHD 2.54 mm Angled Dual Pin Header; Manufacturer: Würth Elektronik eiSos GmbH; ComponentLink1 Description: Manufacturer; ComponentLink2 Description: Datasheet; NoPins: 06
footprint 61300621021 (06 pins, dual row, right angled, gold plating)
pins: 1, 2, 3, 4, 5, 6

## WE-2.54 mm Pin Header & Jumper 61300821021
designator C?
WR-PHD 2.54 mm Angled Dual Pin Header; Manufacturer: Würth Elektronik eiSos GmbH; ComponentLink1 Description: Manufacturer; ComponentLink2 Description: Datasheet; NoPins: 08
footprint 61300821021 (08 pins, dual row, right angled, gold plating)
pins: 1, 2, 3, 4, 5, 6, 7, 8

## WE-2.54 mm Pin Header & Jumper 61301021021
designator C?
WR-PHD 2.54 mm Angled Dual Pin Header; Manufacturer: Würth Elektronik eiSos GmbH; ComponentLink1 Description: Manufacturer; ComponentLink2 Description: Datasheet; NoPins: 10
footprint 61301021021 (10 pins, dual row, right angled, gold plating)
pins: 1, 2, 3, 4, 5, 6, 7, 8, 9, 10

## WE-2.54 mm Pin Header & Jumper 61301221021
designator C?
WR-PHD 2.54 mm Angled Dual Pin Header; Manufacturer: Würth Elektronik eiSos GmbH; ComponentLink1 Description: Manufacturer; ComponentLink2 Description: Datasheet; NoPins: 12
footprint 61301221021 (12 pins, dual row, right angled, gold plating)
pins: 1, 2, 3, 4, 5, 6, 7, 8, 9, 10, 11, 12

## WE-2.54 mm Pin Header & Jumper 61301421021
designator C?
WR-PHD 2.54 mm Angled Dual Pin Header; Manufacturer: Würth Elektronik eiSos GmbH; ComponentLink1 Description: Manufacturer; ComponentLink2 Description: Datasheet; NoPins: 07
footprint 61301421021 (14 pins, dual row, right angled, gold plating)
pins: 1, 2, 3, 4, 5, 6, 7, 8, 9, 10, 11, 12, 13, 14

## WE-2.54 mm Pin Header & Jumper 61301621021
designator C?
WR-PHD 2.54 mm Angled Dual Pin Header; Manufacturer: Würth Elektronik eiSos GmbH; ComponentLink1 Description: Manufacturer; ComponentLink2 Description: Datasheet; NoPins: 16
footprint 61301621021 (16 pins, dual row, right angled, gold plating)
pins: 1, 2, 3, 4, 5, 6, 7, 8, 9, 10, 11, 12, 13, 14, 15, 16

## WE-2.54 mm Pin Header & Jumper 61301821021
designator C?
WR-PHD 2.54 mm Angled Dual Pin Header; Manufacturer: Würth Elektronik eiSos GmbH; ComponentLink1 Description: Manufacturer; ComponentLink2 Description: Datasheet; NoPins: 18
footprint 61301821021 (18 pins, dual row, right angled, gold plating)
pins: 1, 2, 3, 4, 5, 6, 7, 8, 9, 10, 11, 12, 13, 14, 15, 16, 17, 18

## WE-2.54 mm Pin Header & Jumper 61302021021
designator C?
WR-PHD 2.54 mm Angled Dual Pin Header; Manufacturer: Würth Elektronik eiSos GmbH; ComponentLink1 Description: Manufacturer; ComponentLink2 Description: Datasheet; NoPins: 20
footprint 61302021021 (20 pins, dual row, right angled, gold plating)
pins: 1, 2, 3, 4, 5, 6, 7, 8, 9, 10, 11, 12, 13, 14, 15, 16, 17, 18, 19, 20

## WE-2.54 mm Pin Header & Jumper 61302221021
designator C?
WR-PHD 2.54 mm Angled Dual Pin Header; Manufacturer: Würth Elektronik eiSos GmbH; ComponentLink1 Description: Manufacturer; ComponentLink2 Description: Datasheet; NoPins: 22
footprint 61302221021 (22 pins, dual row, right angled, gold plating)
pins: 1, 2, 3, 4, 5, 6, 7, 8, 9, 10, 11, 12, 13, 14, 15, 16, 17, 18, 19, 20, 21, 22

## WE-2.54 mm Pin Header & Jumper 61302421021
designator C?
WR-PHD 2.54 mm Angled Dual Pin Header; Manufacturer: Würth Elektronik eiSos GmbH; ComponentLink1 Description: Manufacturer; ComponentLink2 Description: Datasheet; NoPins: 24
footprint 61302421021 (24 pins, dual row, right angled, gold plating)
pins: 1, 2, 3, 4, 5, 6, 7, 8, 9, 10, 11, 12, 13, 14, 15, 16, 17, 18, 19, 20, 21, 22, 23, 24

## WE-2.54 mm Pin Header & Jumper 61302621021
designator C?
WR-PHD 2.54 mm Angled Dual Pin Header; Manufacturer: Würth Elektronik eiSos GmbH; ComponentLink1 Description: Manufacturer; ComponentLink2 Description: Datasheet; NoPins: 26
footprint 61302621021 (26 pins, dual row, right angled, gold plating)
pins: 1, 2, 3, 4, 5, 6, 7, 8, 9, 10, 11, 12, 13, 14, 15, 16, 17, 18, 19, 20, 21, 22, 23, 24, 25, 26

## WE-2.54 mm Pin Header & Jumper 61303221021
designator C?
WR-PHD 2.54 mm Angled Dual Pin Header; Manufacturer: Würth Elektronik eiSos GmbH; ComponentLink1 Description: Manufacturer; ComponentLink2 Description: Datasheet; NoPins: 32
footprint 61303221021 (32 pins, dual row, right angled, gold plating)
pins: 1, 2, 3, 4, 5, 6, 7, 8, 9, 10, 11, 12, 13, 14, 15, 16, 17, 18, 19, 20, 21, 22, 23, 24, 25, 26, 27, 28, 29, 30, 31, 32

## WE-2.54 mm Pin Header & Jumper 61303421021
designator C?
WR-PHD 2.54 mm Angled Dual Pin Header; Manufacturer: Würth Elektronik eiSos GmbH; ComponentLink1 Description: Manufacturer; ComponentLink2 Description: Datasheet; NoPins: 34
footprint 61303421021 (34 pins, dual row, right angled, gold plating)
pins: 1, 2, 3, 4, 5, 6, 7, 8, 9, 10, 11, 12, 13, 14, 15, 16, 17, 18, 19, 20, 21, 22, 23, 24, 25, 26, 27, 28, 29, 30, 31, 32, 33, 34

## WE-2.54 mm Pin Header & Jumper 61303621021
designator C?
WR-PHD 2.54 mm Angled Dual Pin Header; Manufacturer: Würth Elektronik eiSos GmbH; ComponentLink1 Description: Manufacturer; ComponentLink2 Description: Datasheet; NoPins: 36
footprint 61303621021 (36 pins, dual row, right angled, gold plating)
pins: 1, 2, 3, 4, 5, 6, 7, 8, 9, 10, 11, 12, 13, 14, 15, 16, 17, 18, 19, 20, 21, 22, 23, 24, 25, 26, 27, 28, 29, 30, 31, 32, 33, 34, 35, 36

## WE-2.54 mm Pin Header & Jumper 61304021021
designator C?
WR-PHD 2.54 mm Angled Dual Pin Header; Manufacturer: Würth Elektronik eiSos GmbH; ComponentLink1 Description: Manufacturer; ComponentLink2 Description: Datasheet; NoPins: 40
footprint 61304021021 (40 pins, dual row, right angled, gold plating)
pins: 1, 2, 3, 4, 5, 6, 7, 8, 9, 10, 11, 12, 13, 14, 15, 16, 17, 18, 19, 20, 21, 22, 23, 24, 25, 26, 27, 28, 29, 30, 31, 32, 33, 34, 35, 36, 37, 38, 39, 40

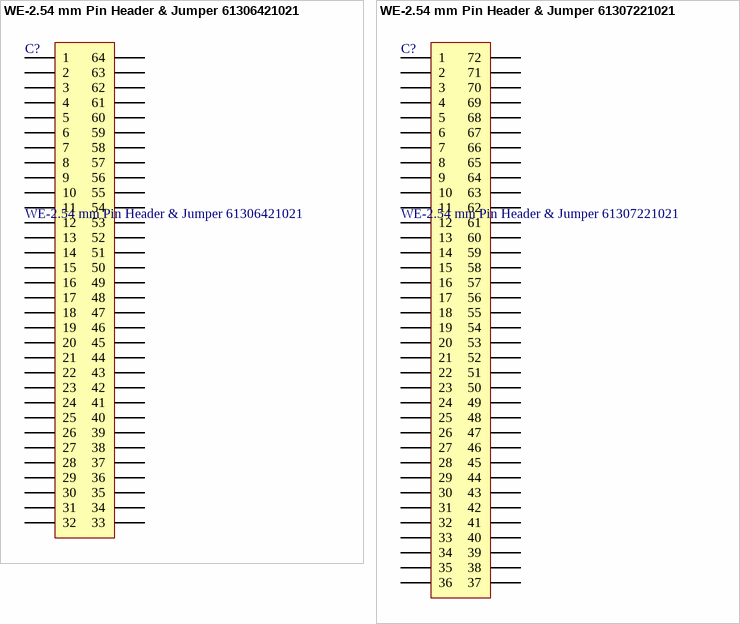
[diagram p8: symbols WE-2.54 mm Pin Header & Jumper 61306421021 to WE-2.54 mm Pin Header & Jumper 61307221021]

## WE-2.54 mm Pin Header & Jumper 61306421021
designator C?
WR-PHD 2.54 mm Angled Dual Pin Header; Manufacturer: Würth Elektronik eiSos GmbH; ComponentLink1 Description: Manufacturer; ComponentLink2 Description: Datasheet; NoPins: 64
footprint 61306421021 (64 pins, dual row, right angled, gold plating)
pins: 1, 2, 3, 4, 5, 6, 7, 8, 9, 10, 11, 12, 13, 14, 15, 16, 17, 18, 19, 20, 21, 22, 23, 24, 25, 26, 27, 28, 29, 30, 31, 32, 33, 34, 35, 36, 37, 38, 39, 40, 41, 42, 43, 44, 45, 46, 47, 48, 49, 50, 51, 52, 53, 54, 55, 56, 57, 58, 59, 60, 61, 62, 63, 64

## WE-2.54 mm Pin Header & Jumper 61307221021
designator C?
WR-PHD 2.54 mm Angled Dual Pin Header; Manufacturer: Würth Elektronik eiSos GmbH; ComponentLink1 Description: Manufacturer; ComponentLink2 Description: Datasheet; NoPins: 72
footprint 61307221021 (72 pins, dual row, right angled, gold plating)
pins: 1, 2, 3, 4, 5, 6, 7, 8, 9, 10, 11, 12, 13, 14, 15, 16, 17, 18, 19, 20, 21, 22, 23, 24, 25, 26, 27, 28, 29, 30, 31, 32, 33, 34, 35, 36, 37, 38, 39, 40, 41, 42, 43, 44, 45, 46, 47, 48, 49, 50, 51, 52, 53, 54, 55, 56, 57, 58, 59, 60, 61, 62, 63, 64, 65, 66, 67, 68, 69, 70, 71, 72


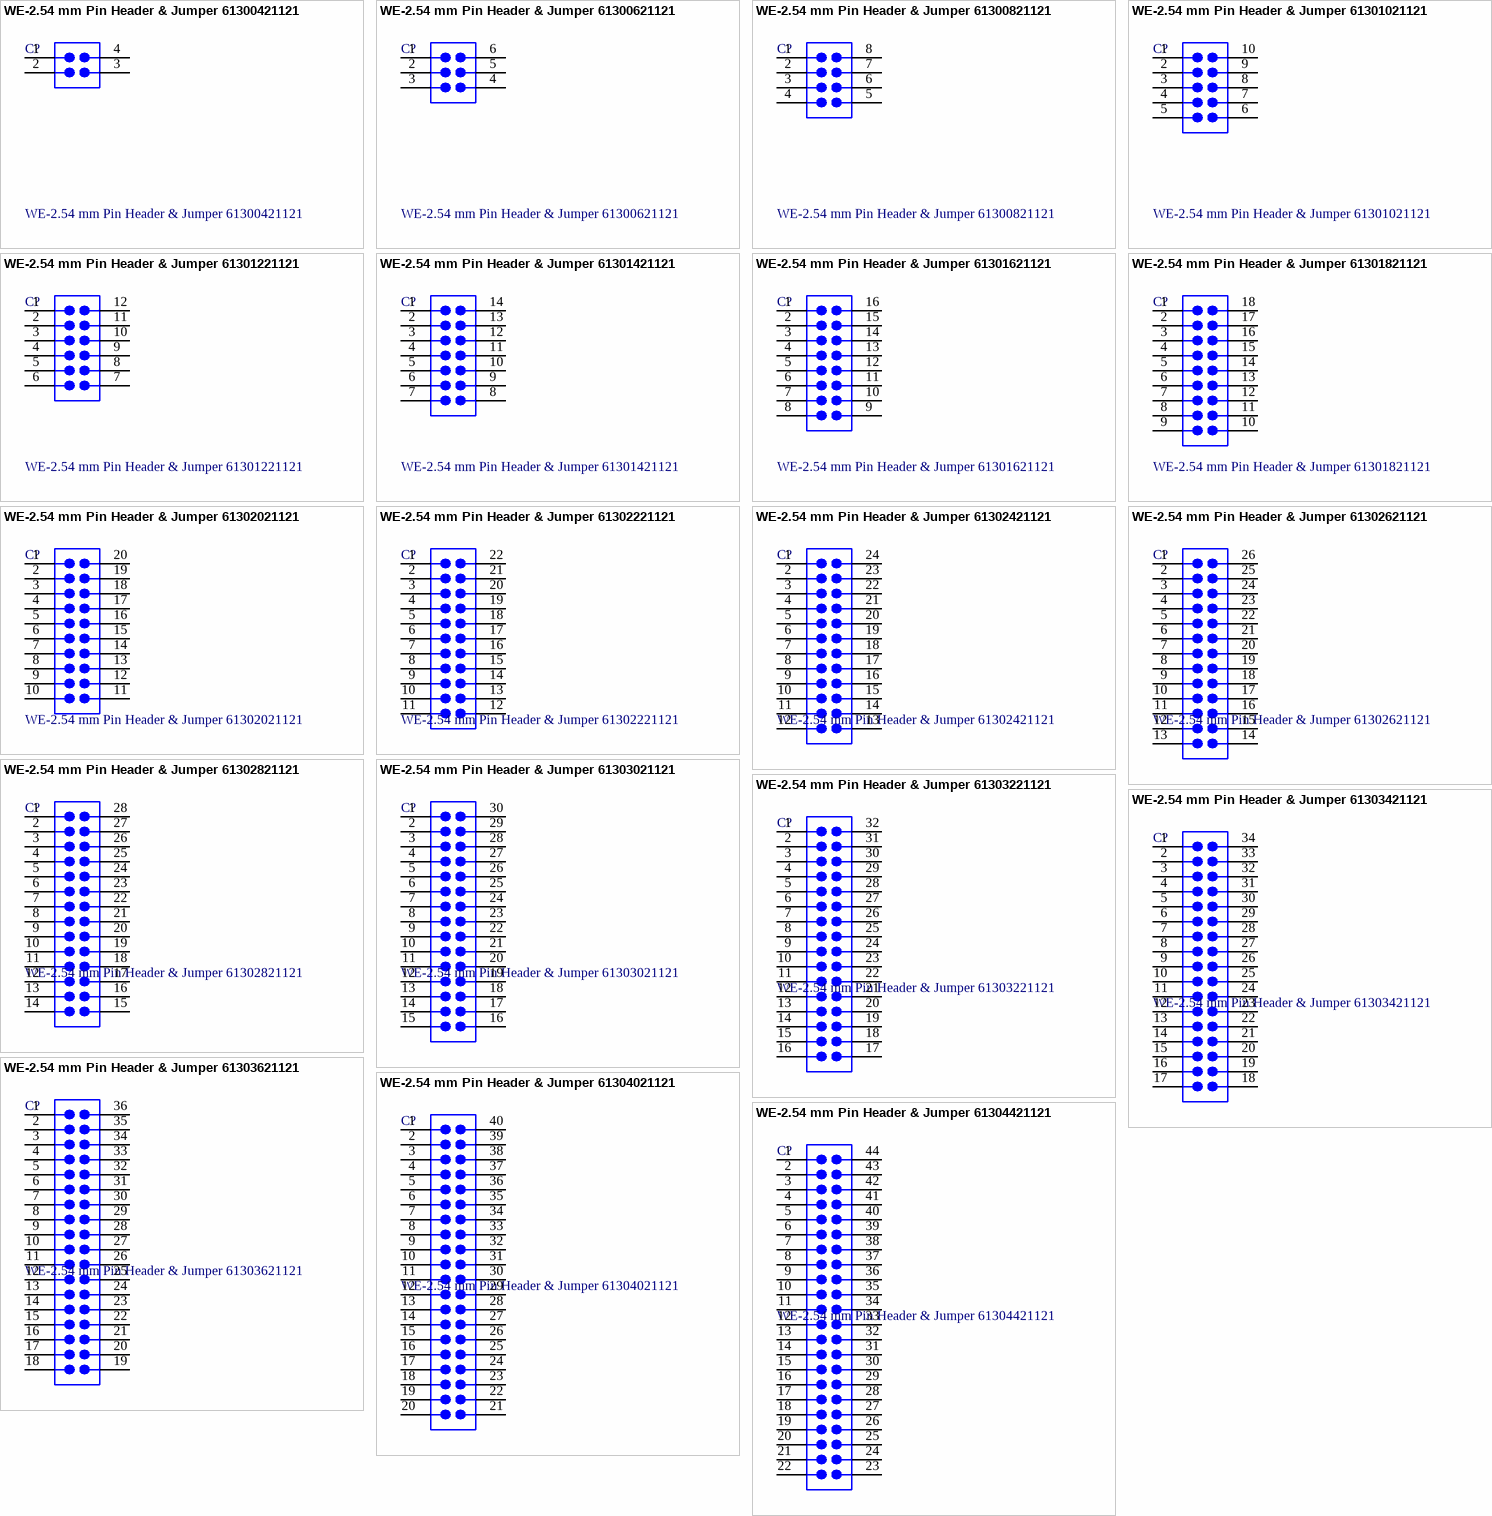
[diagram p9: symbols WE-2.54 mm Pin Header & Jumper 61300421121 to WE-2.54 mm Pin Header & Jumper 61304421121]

## WE-2.54 mm Pin Header & Jumper 61300421121
designator C?
WR-PHD 2.54 mm Dual Pin Header; Manufacturer: Würth Elektronik eiSos GmbH; ComponentLink1 Description: Manufacturer; ComponentLink2 Description: Datasheet; NoPins: 04
footprint 61300421121 (4 pins, dual pin, straight, gold plating)
pins: 1, 2, 3, 4

## WE-2.54 mm Pin Header & Jumper 61300621121
designator C?
WR-PHD 2.54 mm Dual Pin Header; Manufacturer: Würth Elektronik eiSos GmbH; ComponentLink1 Description: Manufacturer; ComponentLink2 Description: Datasheet; NoPins: 06
footprint 61300621121 (6 pins, dual pin, straight, gold plating)
pins: 1, 2, 3, 4, 5, 6

## WE-2.54 mm Pin Header & Jumper 61300821121
designator C?
WR-PHD 2.54 mm Dual Pin Header; Manufacturer: Würth Elektronik eiSos GmbH; ComponentLink1 Description: Manufacturer; ComponentLink2 Description: Datasheet; NoPins: 08
footprint 61300821121 (8 pins, dual pin, straight, gold plating)
pins: 1, 2, 3, 4, 5, 6, 7, 8

## WE-2.54 mm Pin Header & Jumper 61301021121
designator C?
WR-PHD 2.54 mm Dual Pin Header; Manufacturer: Würth Elektronik eiSos GmbH; ComponentLink1 Description: Manufacturer; ComponentLink2 Description: Datasheet; NoPins: 10
footprint 61301021121 (10 pins, dual pin, straight, gold plating)
pins: 1, 2, 3, 4, 5, 6, 7, 8, 9, 10

## WE-2.54 mm Pin Header & Jumper 61301221121
designator C?
WR-PHD 2.54 mm Dual Pin Header; Manufacturer: Würth Elektronik eiSos GmbH; ComponentLink1 Description: Manufacturer; ComponentLink2 Description: Datasheet; NoPins: 12
footprint 61301221121 (12 pins, dual pin, straight, gold plating)
pins: 1, 2, 3, 4, 5, 6, 7, 8, 9, 10, 11, 12

## WE-2.54 mm Pin Header & Jumper 61301421121
designator C?
WR-PHD 2.54 mm Dual Pin Header; Manufacturer: Würth Elektronik eiSos GmbH; ComponentLink1 Description: Manufacturer; ComponentLink2 Description: Datasheet; NoPins: 14
footprint 61301421121 (14 pins, dual pin, straight, gold plating)
pins: 1, 2, 3, 4, 5, 6, 7, 8, 9, 10, 11, 12, 13, 14

## WE-2.54 mm Pin Header & Jumper 61301621121
designator C?
WR-PHD 2.54 mm Dual Pin Header; Manufacturer: Würth Elektronik eiSos GmbH; ComponentLink1 Description: Manufacturer; ComponentLink2 Description: Datasheet; NoPins: 16
footprint 61301621121 (16 pins, dual pin, straight, gold plating)
pins: 1, 2, 3, 4, 5, 6, 7, 8, 9, 10, 11, 12, 13, 14, 15, 16

## WE-2.54 mm Pin Header & Jumper 61301821121
designator C?
WR-PHD 2.54 mm Dual Pin Header; Manufacturer: Würth Elektronik eiSos GmbH; ComponentLink1 Description: Manufacturer; ComponentLink2 Description: Datasheet; NoPins: 18
footprint 61301821121 (18 pins, dual pin, straight, gold plating)
pins: 1, 2, 3, 4, 5, 6, 7, 8, 9, 10, 11, 12, 13, 14, 15, 16, 17, 18

## WE-2.54 mm Pin Header & Jumper 61302021121
designator C?
WR-PHD 2.54 mm Dual Pin Header; Manufacturer: Würth Elektronik eiSos GmbH; ComponentLink1 Description: Manufacturer; ComponentLink2 Description: Datasheet; NoPins: 20
footprint 61302021121 (20 pins, dual pin, straight, gold plating)
pins: 1, 2, 3, 4, 5, 6, 7, 8, 9, 10, 11, 12, 13, 14, 15, 16, 17, 18, 19, 20

## WE-2.54 mm Pin Header & Jumper 61302221121
designator C?
WR-PHD 2.54 mm Dual Pin Header; Manufacturer: Würth Elektronik eiSos GmbH; ComponentLink1 Description: Manufacturer; ComponentLink2 Description: Datasheet; NoPins: 22
footprint 61302221121 (24 pins, dual pin, straight, gold plating)
pins: 1, 2, 3, 4, 5, 6, 7, 8, 9, 10, 11, 12, 13, 14, 15, 16, 17, 18, 19, 20, 21, 22

## WE-2.54 mm Pin Header & Jumper 61302421121
designator C?
WR-PHD 2.54 mm Dual Pin Header; Manufacturer: Würth Elektronik eiSos GmbH; ComponentLink1 Description: Manufacturer; ComponentLink2 Description: Datasheet; NoPins: 24
footprint 61302421121 (24 pins, dual pin, straight, gold plating)
pins: 1, 2, 3, 4, 5, 6, 7, 8, 9, 10, 11, 12, 13, 14, 15, 16, 17, 18, 19, 20, 21, 22, 23, 24

## WE-2.54 mm Pin Header & Jumper 61302621121
designator C?
WR-PHD 2.54 mm Dual Pin Header; Manufacturer: Würth Elektronik eiSos GmbH; ComponentLink1 Description: Manufacturer; ComponentLink2 Description: Datasheet; NoPins: 26
footprint 61302621121 (28 pins, dual pin, straight, gold plating)
pins: 1, 2, 3, 4, 5, 6, 7, 8, 9, 10, 11, 12, 13, 14, 15, 16, 17, 18, 19, 20, 21, 22, 23, 24, 25, 26

## WE-2.54 mm Pin Header & Jumper 61302821121
designator C?
WR-PHD 2.54 mm Dual Pin Header; Manufacturer: Würth Elektronik eiSos GmbH; ComponentLink1 Description: Manufacturer; ComponentLink2 Description: Datasheet; NoPins: 28
footprint 61302821121 (28 pins, dual pin, straight, gold plating)
pins: 1, 2, 3, 4, 5, 6, 7, 8, 9, 10, 11, 12, 13, 14, 15, 16, 17, 18, 19, 20, 21, 22, 23, 24, 25, 26, 27, 28

## WE-2.54 mm Pin Header & Jumper 61303021121
designator C?
WR-PHD 2.54 mm Dual Pin Header; Manufacturer: Würth Elektronik eiSos GmbH; ComponentLink1 Description: Manufacturer; ComponentLink2 Description: Datasheet; NoPins: 30
footprint 61303021121 (30 pins, dual pin, straight, gold plating)
pins: 1, 2, 3, 4, 5, 6, 7, 8, 9, 10, 11, 12, 13, 14, 15, 16, 17, 18, 19, 20, 21, 22, 23, 24, 25, 26, 27, 28, 29, 30

## WE-2.54 mm Pin Header & Jumper 61303221121
designator C?
WR-PHD 2.54 mm Dual Pin Header; Manufacturer: Würth Elektronik eiSos GmbH; ComponentLink1 Description: Manufacturer; ComponentLink2 Description: Datasheet; NoPins: 32
footprint 61303221121 (32 pins, dual pin, straight, gold plating)
pins: 1, 2, 3, 4, 5, 6, 7, 8, 9, 10, 11, 12, 13, 14, 15, 16, 17, 18, 19, 20, 21, 22, 23, 24, 25, 26, 27, 28, 29, 30, 31, 32

## WE-2.54 mm Pin Header & Jumper 61303421121
designator C?
WR-PHD 2.54 mm Dual Pin Header; Manufacturer: Würth Elektronik eiSos GmbH; ComponentLink1 Description: Manufacturer; ComponentLink2 Description: Datasheet; NoPins: 34
footprint 61303421121 (34 pins, dual pin, straight, gold plating)
pins: 1, 2, 3, 4, 5, 6, 7, 8, 9, 10, 11, 12, 13, 14, 15, 16, 17, 18, 19, 20, 21, 22, 23, 24, 25, 26, 27, 28, 29, 30, 31, 32, 33, 34

## WE-2.54 mm Pin Header & Jumper 61303621121
designator C?
WR-PHD 2.54 mm Dual Pin Header; Manufacturer: Würth Elektronik eiSos GmbH; ComponentLink1 Description: Manufacturer; ComponentLink2 Description: Datasheet; NoPins: 36
footprint 61303621121 (36 pins, dual pin, straight, gold plating)
pins: 1, 2, 3, 4, 5, 6, 7, 8, 9, 10, 11, 12, 13, 14, 15, 16, 17, 18, 19, 20, 21, 22, 23, 24, 25, 26, 27, 28, 29, 30, 31, 32, 33, 34, 35, 36

## WE-2.54 mm Pin Header & Jumper 61304021121
designator C?
WR-PHD 2.54 mm Dual Pin Header; Manufacturer: Würth Elektronik eiSos GmbH; ComponentLink1 Description: Manufacturer; ComponentLink2 Description: Datasheet; NoPins: 40
footprint 61304021121 (40 pins, dual pin, straight, gold plating)
pins: 1, 2, 3, 4, 5, 6, 7, 8, 9, 10, 11, 12, 13, 14, 15, 16, 17, 18, 19, 20, 21, 22, 23, 24, 25, 26, 27, 28, 29, 30, 31, 32, 33, 34, 35, 36, 37, 38, 39, 40

## WE-2.54 mm Pin Header & Jumper 61304421121
designator C?
WR-PHD 2.54 mm Dual Pin Header; Manufacturer: Würth Elektronik eiSos GmbH; ComponentLink1 Description: Manufacturer; ComponentLink2 Description: Datasheet; NoPins: 44
footprint 61304421121 (44 pins, dual pin, straight, gold plating)
pins: 1, 2, 3, 4, 5, 6, 7, 8, 9, 10, 11, 12, 13, 14, 15, 16, 17, 18, 19, 20, 21, 22, 23, 24, 25, 26, 27, 28, 29, 30, 31, 32, 33, 34, 35, 36, 37, 38, 39, 40, 41, 42, 43, 44

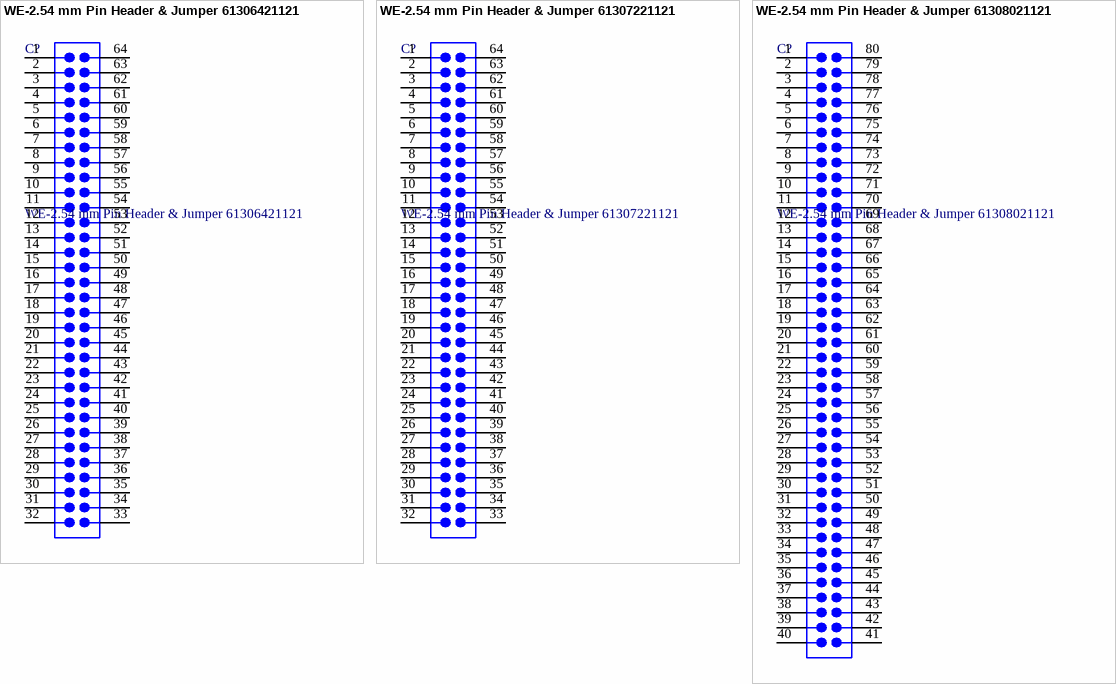
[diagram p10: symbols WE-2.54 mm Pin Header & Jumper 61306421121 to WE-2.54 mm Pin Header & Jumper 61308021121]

## WE-2.54 mm Pin Header & Jumper 61306421121
designator C?
WR-PHD 2.54 mm Dual Pin Header; Manufacturer: Würth Elektronik eiSos GmbH; ComponentLink1 Description: Manufacturer; ComponentLink2 Description: Datasheet; NoPins: 64
footprint 61306421121 (64 pins, dual pin, straight, gold plating)
pins: 1, 2, 3, 4, 5, 6, 7, 8, 9, 10, 11, 12, 13, 14, 15, 16, 17, 18, 19, 20, 21, 22, 23, 24, 25, 26, 27, 28, 29, 30, 31, 32, 33, 34, 35, 36, 37, 38, 39, 40, 41, 42, 43, 44, 45, 46, 47, 48, 49, 50, 51, 52, 53, 54, 55, 56, 57, 58, 59, 60, 61, 62, 63, 64

## WE-2.54 mm Pin Header & Jumper 61307221121
designator C?
WR-PHD 2.54 mm Dual Pin Header; Manufacturer: Würth Elektronik eiSos GmbH; ComponentLink1 Description: Manufacturer; ComponentLink2 Description: Datasheet; NoPins: 72
footprint 61307221121 (72 pins, dual pin, straight, gold plating)
pins: 1, 2, 3, 4, 5, 6, 7, 8, 9, 10, 11, 12, 13, 14, 15, 16, 17, 18, 19, 20, 21, 22, 23, 24, 25, 26, 27, 28, 29, 30, 31, 32, 33, 34, 35, 36, 37, 38, 39, 40, 41, 42, 43, 44, 45, 46, 47, 48, 49, 50, 51, 52, 53, 54, 55, 56, 57, 58, 59, 60, 61, 62, 63, 64

## WE-2.54 mm Pin Header & Jumper 61308021121
designator C?
WR-PHD 2.54 mm Dual Pin Header; Manufacturer: Würth Elektronik eiSos GmbH; ComponentLink1 Description: Manufacturer; ComponentLink2 Description: Datasheet; NoPins: 80
footprint 61308021121 (80 pins, dual row, right angled, gold plating)
pins: 1, 2, 3, 4, 5, 6, 7, 8, 9, 10, 11, 12, 13, 14, 15, 16, 17, 18, 19, 20, 21, 22, 23, 24, 25, 26, 27, 28, 29, 30, 31, 32, 33, 34, 35, 36, 37, 38, 39, 40, 41, 42, 43, 44, 45, 46, 47, 48, 49, 50, 51, 52, 53, 54, 55, 56, 57, 58, 59, 60, 61, 62, 63, 64, 65, 66, 67, 68, 69, 70, 71, 72, 73, 74, 75, 76, 77, 78, 79, 80


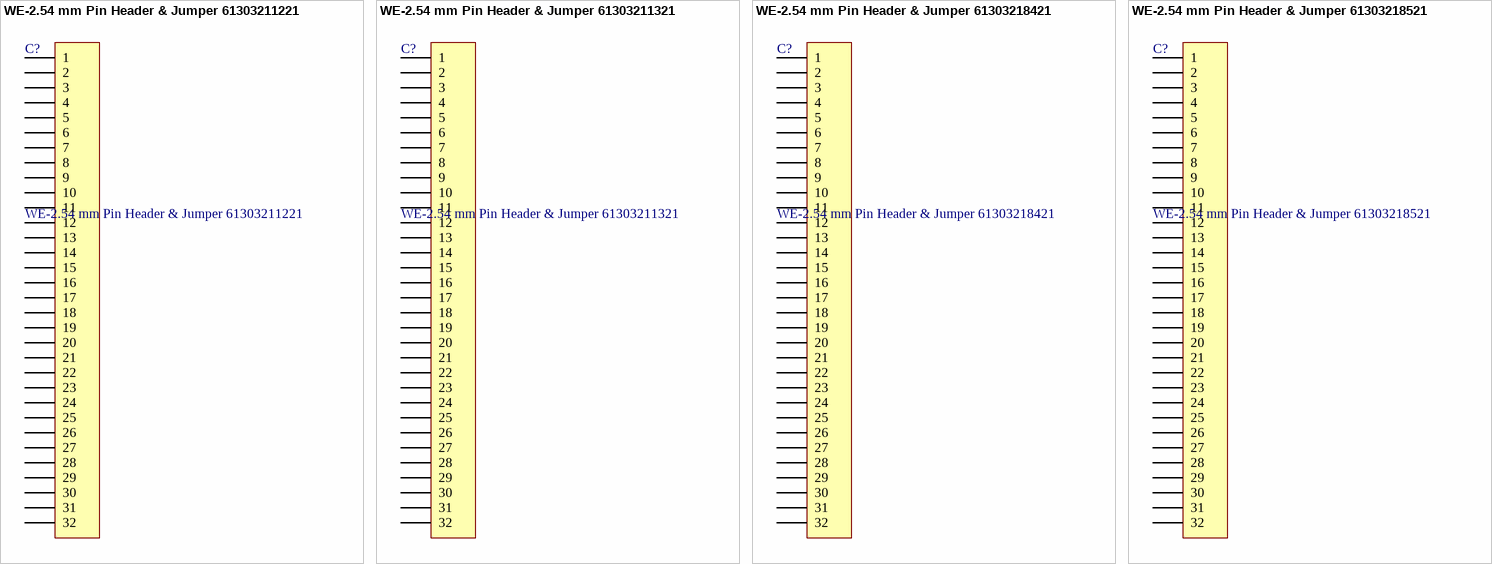
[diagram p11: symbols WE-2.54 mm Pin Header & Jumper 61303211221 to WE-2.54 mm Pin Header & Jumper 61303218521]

## WE-2.54 mm Pin Header & Jumper 61303211221
designator C?
WR-PHD 2.54 mm Board Stacker; Manufacturer: Würth Elektronik eiSos GmbH; ComponentLink1 Description: Manufacturer; ComponentLink2 Description: Datasheet; NoPins: 32
footprint 61303211221 (32 pins, 1 row, gold plating)
pins: 1, 2, 3, 4, 5, 6, 7, 8, 9, 10, 11, 12, 13, 14, 15, 16, 17, 18, 19, 20, 21, 22, 23, 24, 25, 26, 27, 28, 29, 30, 31, 32

## WE-2.54 mm Pin Header & Jumper 61303211321
designator C?
WR-PHD 2.54 mm Board Stacker; Manufacturer: Würth Elektronik eiSos GmbH; ComponentLink1 Description: Manufacturer; ComponentLink2 Description: Datasheet; NoPins: 32
footprint 61303211321 (32 pins, 1 row, gold plating)
pins: 1, 2, 3, 4, 5, 6, 7, 8, 9, 10, 11, 12, 13, 14, 15, 16, 17, 18, 19, 20, 21, 22, 23, 24, 25, 26, 27, 28, 29, 30, 31, 32

## WE-2.54 mm Pin Header & Jumper 61303218421
designator C?
WR-PHD 2.54 mm Board Stacker; Manufacturer: Würth Elektronik eiSos GmbH; ComponentLink1 Description: Manufacturer; ComponentLink2 Description: Datasheet; NoPins: 32
footprint 61303218421 (32 pins, 1 row, gold plating)
pins: 1, 2, 3, 4, 5, 6, 7, 8, 9, 10, 11, 12, 13, 14, 15, 16, 17, 18, 19, 20, 21, 22, 23, 24, 25, 26, 27, 28, 29, 30, 31, 32

## WE-2.54 mm Pin Header & Jumper 61303218521
designator C?
WR-PHD 2.54 mm Board Stacker; Manufacturer: Würth Elektronik eiSos GmbH; ComponentLink1 Description: Manufacturer; ComponentLink2 Description: Datasheet; NoPins: 32
footprint 61303218521 (32 pins, 1 row, gold plating)
pins: 1, 2, 3, 4, 5, 6, 7, 8, 9, 10, 11, 12, 13, 14, 15, 16, 17, 18, 19, 20, 21, 22, 23, 24, 25, 26, 27, 28, 29, 30, 31, 32


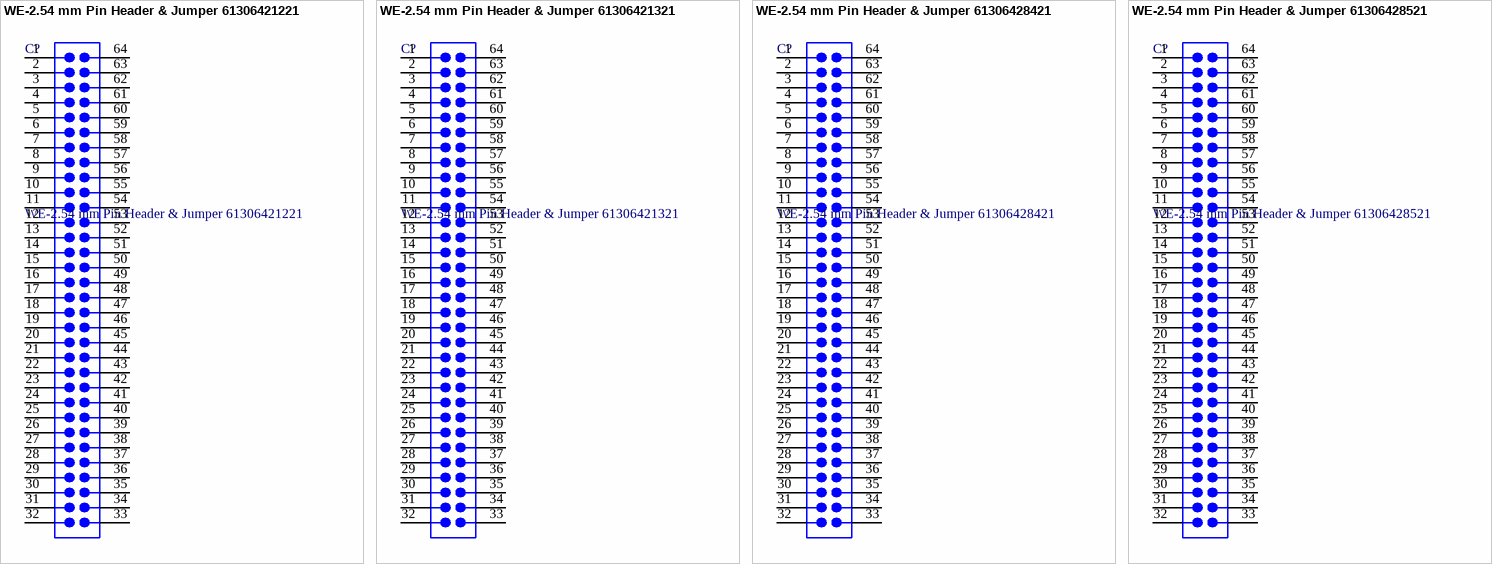
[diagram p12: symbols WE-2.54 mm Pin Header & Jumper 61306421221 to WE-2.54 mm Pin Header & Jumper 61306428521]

## WE-2.54 mm Pin Header & Jumper 61306421221
designator C?
WR-PHD 2.54 mm Dual Board Stacker; Manufacturer: Würth Elektronik eiSos GmbH; ComponentLink1 Description: Manufacturer; ComponentLink2 Description: Datasheet; NoPins: 64
footprint 61306421221 (64 pins, dual row, gold plating)
pins: 1, 2, 3, 4, 5, 6, 7, 8, 9, 10, 11, 12, 13, 14, 15, 16, 17, 18, 19, 20, 21, 22, 23, 24, 25, 26, 27, 28, 29, 30, 31, 32, 33, 34, 35, 36, 37, 38, 39, 40, 41, 42, 43, 44, 45, 46, 47, 48, 49, 50, 51, 52, 53, 54, 55, 56, 57, 58, 59, 60, 61, 62, 63, 64

## WE-2.54 mm Pin Header & Jumper 61306421321
designator C?
WR-PHD 2.54 mm Dual Board Stacker; Manufacturer: Würth Elektronik eiSos GmbH; ComponentLink1 Description: Manufacturer; ComponentLink2 Description: Datasheet; NoPins: 64
footprint 61306421321 (64 pins, dual row, gold plating)
pins: 1, 2, 3, 4, 5, 6, 7, 8, 9, 10, 11, 12, 13, 14, 15, 16, 17, 18, 19, 20, 21, 22, 23, 24, 25, 26, 27, 28, 29, 30, 31, 32, 33, 34, 35, 36, 37, 38, 39, 40, 41, 42, 43, 44, 45, 46, 47, 48, 49, 50, 51, 52, 53, 54, 55, 56, 57, 58, 59, 60, 61, 62, 63, 64

## WE-2.54 mm Pin Header & Jumper 61306428421
designator C?
WR-PHD 2.54 mm Dual Board Stacker; Manufacturer: Würth Elektronik eiSos GmbH; ComponentLink1 Description: Manufacturer; ComponentLink2 Description: Datasheet; NoPins: 64
footprint 61306428421 (64 pins, dual row, gold plating)
pins: 1, 2, 3, 4, 5, 6, 7, 8, 9, 10, 11, 12, 13, 14, 15, 16, 17, 18, 19, 20, 21, 22, 23, 24, 25, 26, 27, 28, 29, 30, 31, 32, 33, 34, 35, 36, 37, 38, 39, 40, 41, 42, 43, 44, 45, 46, 47, 48, 49, 50, 51, 52, 53, 54, 55, 56, 57, 58, 59, 60, 61, 62, 63, 64

## WE-2.54 mm Pin Header & Jumper 61306428521
designator C?
WR-PHD 2.54 mm Dual Board Stacker; Manufacturer: Würth Elektronik eiSos GmbH; ComponentLink1 Description: Manufacturer; ComponentLink2 Description: Datasheet; NoPins: 64
footprint 61306428521 (64 pins, dual row, gold plating)
pins: 1, 2, 3, 4, 5, 6, 7, 8, 9, 10, 11, 12, 13, 14, 15, 16, 17, 18, 19, 20, 21, 22, 23, 24, 25, 26, 27, 28, 29, 30, 31, 32, 33, 34, 35, 36, 37, 38, 39, 40, 41, 42, 43, 44, 45, 46, 47, 48, 49, 50, 51, 52, 53, 54, 55, 56, 57, 58, 59, 60, 61, 62, 63, 64


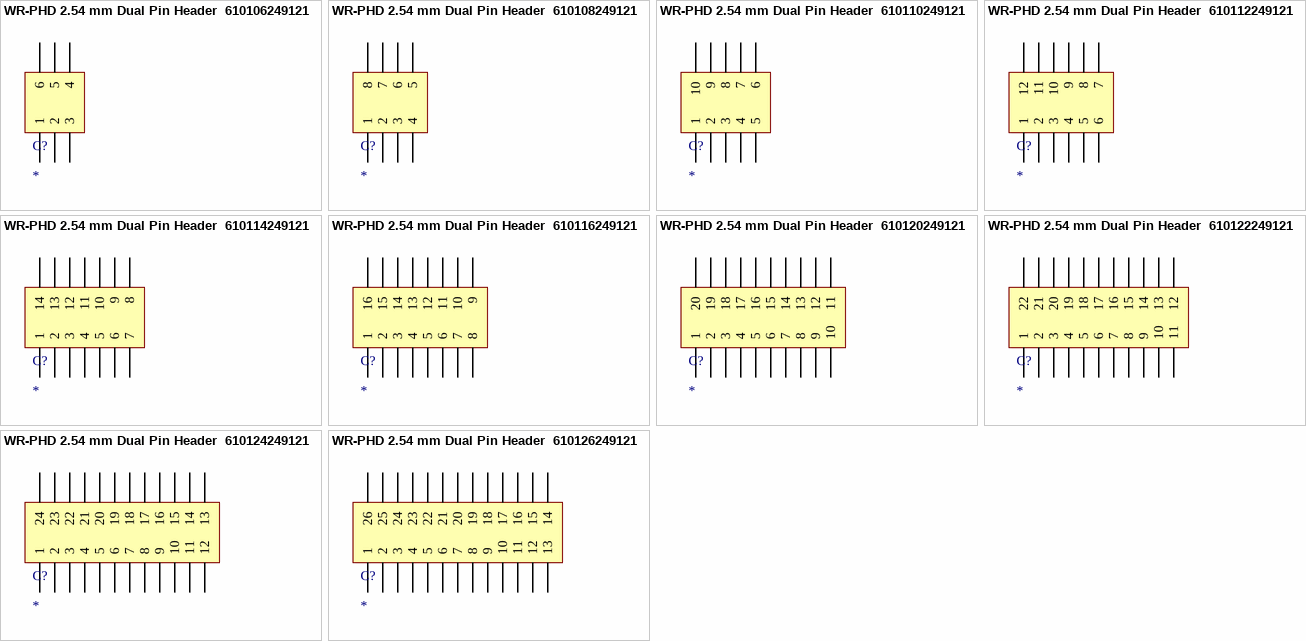
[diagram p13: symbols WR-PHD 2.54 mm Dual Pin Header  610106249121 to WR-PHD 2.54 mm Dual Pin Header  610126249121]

## WR-PHD 2.54 mm Dual Pin Header  610106249121
designator C?
WR-PHD 2.54 mm Dual Pin Header; Manufacturer: Würth Elektronik eiSos GmbH; partNo: 610106249121; ComponentLink1 Description: Manufacturer; ComponentLink2 Description: Datasheet; NoPins: 6
footprint 610106249121
pins: 1, 2, 3, 4, 5, 6

## WR-PHD 2.54 mm Dual Pin Header  610108249121
designator C?
WR-PHD 2.54 mm Dual Pin Header; Manufacturer: Würth Elektronik eiSos GmbH; partNo: 610108249121; ComponentLink1 Description: Manufacturer; ComponentLink2 Description: Datasheet; NoPins: 8
footprint 610108249121
pins: 1, 2, 3, 4, 5, 6, 7, 8

## WR-PHD 2.54 mm Dual Pin Header  610110249121
designator C?
WR-PHD 2.54 mm Dual Pin Header; Manufacturer: Würth Elektronik eiSos GmbH; partNo: 610110249121; ComponentLink1 Description: Manufacturer; ComponentLink2 Description: Datasheet; NoPins: 10
footprint 610110249121
pins: 1, 2, 3, 4, 5, 6, 7, 8, 9, 10

## WR-PHD 2.54 mm Dual Pin Header  610112249121
designator C?
WR-PHD 2.54 mm Dual Pin Header; Manufacturer: Würth Elektronik eiSos GmbH; partNo: 610112249121; ComponentLink1 Description: Manufacturer; ComponentLink2 Description: Datasheet; NoPins: 12
footprint 610112249121
pins: 1, 2, 3, 4, 5, 6, 7, 8, 9, 10, 11, 12

## WR-PHD 2.54 mm Dual Pin Header  610114249121
designator C?
WR-PHD 2.54 mm Dual Pin Header; Manufacturer: Würth Elektronik eiSos GmbH; partNo: 610114249121; ComponentLink1 Description: Manufacturer; ComponentLink2 Description: Datasheet; NoPins: 14
footprint 610114249121
pins: 1, 2, 3, 4, 5, 6, 7, 8, 9, 10, 11, 12, 13, 14

## WR-PHD 2.54 mm Dual Pin Header  610116249121
designator C?
WR-PHD 2.54 mm Dual Pin Header; Manufacturer: Würth Elektronik eiSos GmbH; partNo: 610116249121; ComponentLink1 Description: Manufacturer; ComponentLink2 Description: Datasheet; NoPins: 16
footprint 610116249121
pins: 1, 2, 3, 4, 5, 6, 7, 8, 9, 10, 11, 12, 13, 14, 15, 16

## WR-PHD 2.54 mm Dual Pin Header  610120249121
designator C?
WR-PHD 2.54 mm Dual Pin Header; Manufacturer: Würth Elektronik eiSos GmbH; partNo: 610120249121; ComponentLink1 Description: Manufacturer; ComponentLink2 Description: Datasheet; NoPins: 20
footprint 610120249121
pins: 1, 2, 3, 4, 5, 6, 7, 8, 9, 10, 11, 12, 13, 14, 15, 16, 17, 18, 19, 20

## WR-PHD 2.54 mm Dual Pin Header  610122249121
designator C?
WR-PHD 2.54 mm Dual Pin Header; Manufacturer: Würth Elektronik eiSos GmbH; partNo: 610122249121; ComponentLink1 Description: Manufacturer; ComponentLink2 Description: Datasheet; NoPins: 22
footprint 610122249121
pins: 1, 2, 3, 4, 5, 6, 7, 8, 9, 10, 11, 12, 13, 14, 15, 16, 17, 18, 19, 20, 21, 22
